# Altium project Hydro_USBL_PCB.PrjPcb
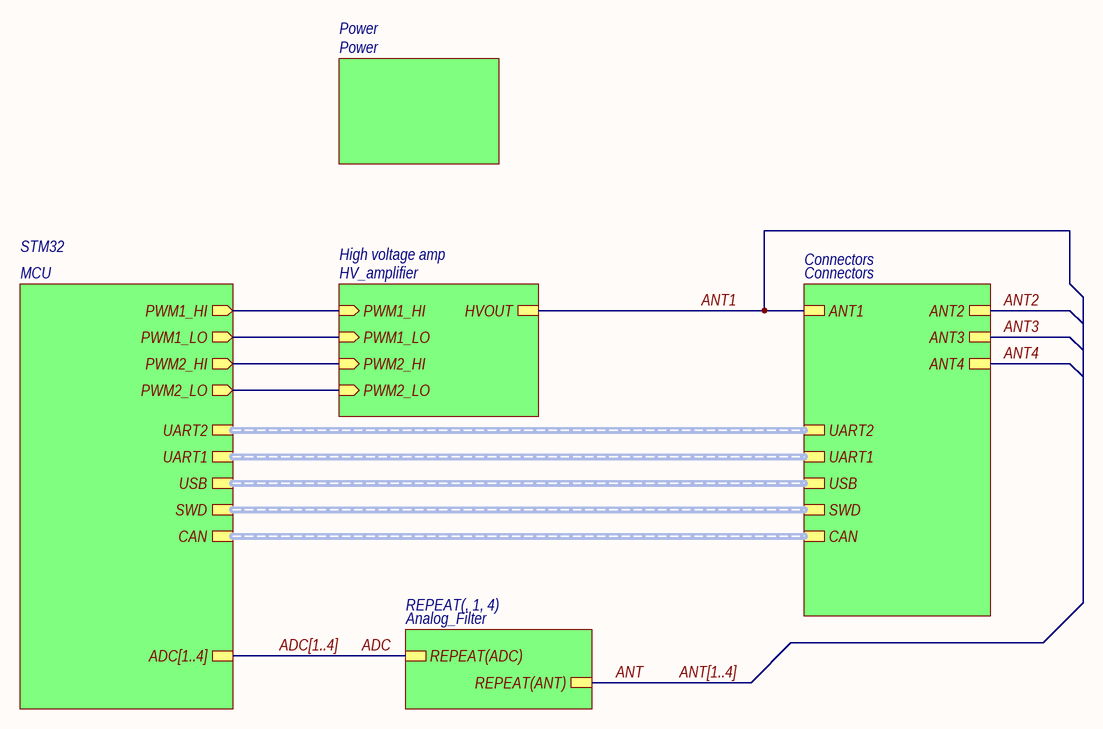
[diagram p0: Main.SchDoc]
Decimal_Number_PCB: ГИДР.123456.XXX; Decimal_Number_Shematic: ГИДР.123456.XXX; DrawnBy: Михайловский Г.; Release_Date: ???; Title: ГАНС с короткой или ультракороткой базой; Title1: Преобразователь из; Title2: 15В в 300В; Version: 01
6 sheets, 273 parts. Net scope: hierarchical (ports join the sheet entries above them; power ports are global).
Board file: Hydro_USBL_PCB.PcbDoc
Sheets:
  Main.SchDoc
    Connectors = Connectors.SchDoc
    1 = Analog_Filter.SchDoc
    2 = Analog_Filter.SchDoc
    3 = Analog_Filter.SchDoc
    4 = Analog_Filter.SchDoc
    Power = Power.SchDoc
    High voltage amp = HV_amplifier.SchDoc
    STM32 = MCU.SchDoc

## Sheet Main.SchDoc: ГАНС с короткой или ультракороткой базой
size 420 x 297 mm; SheetNumber: 1; SheetTotal: 6

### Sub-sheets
Connectors = Connectors: ANT1, ANT2, ANT3, ANT4, SWD (harness SWD), UART2 (harness UART), USB (harness USB), UART1 (harness UART-RS485), CAN (harness CAN)
High voltage amp = HV_amplifier: HVOUT, PWM1_HI (in), PWM1_LO (in), PWM2_HI (in), PWM2_LO (in)
Power = Power: no entries
REPEAT(, 1, 4) = Analog_Filter: REPEAT(ADC), REPEAT(ANT)
STM32 = MCU: PWM1_HI (out), PWM1_LO (out), PWM2_HI (out), PWM2_LO (out), ADC[1..4], UART2 (harness UART), UART1 (harness UART-RS485), USB (harness USB), SWD (harness SWD), CAN (harness CAN)

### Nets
ANT1: sheet Connectors/ANT1, sheet High voltage amp/HVOUT
PWM1_HI: sheet High voltage amp/PWM1_HI, sheet STM32/PWM1_HI
PWM1_LO: sheet High voltage amp/PWM1_LO, sheet STM32/PWM1_LO
PWM2_HI: sheet High voltage amp/PWM2_HI, sheet STM32/PWM2_HI
PWM2_LO: sheet High voltage amp/PWM2_LO, sheet STM32/PWM2_LO

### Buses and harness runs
bus ADC[1..4] = sheet STM32/ADC[1..4]
bus ANT[1..4]
harness sheet Connectors/CAN = sheet STM32/CAN
harness sheet Connectors/SWD = sheet STM32/SWD
harness sheet Connectors/UART1 = sheet STM32/UART1
harness sheet Connectors/UART2 = sheet STM32/UART2
harness sheet Connectors/USB = sheet STM32/USB

## Sheet Connectors.SchDoc: ГАНС с короткой или ультракороткой базой
size 420 x 297 mm; SheetNumber: 6; SheetTotal: 6
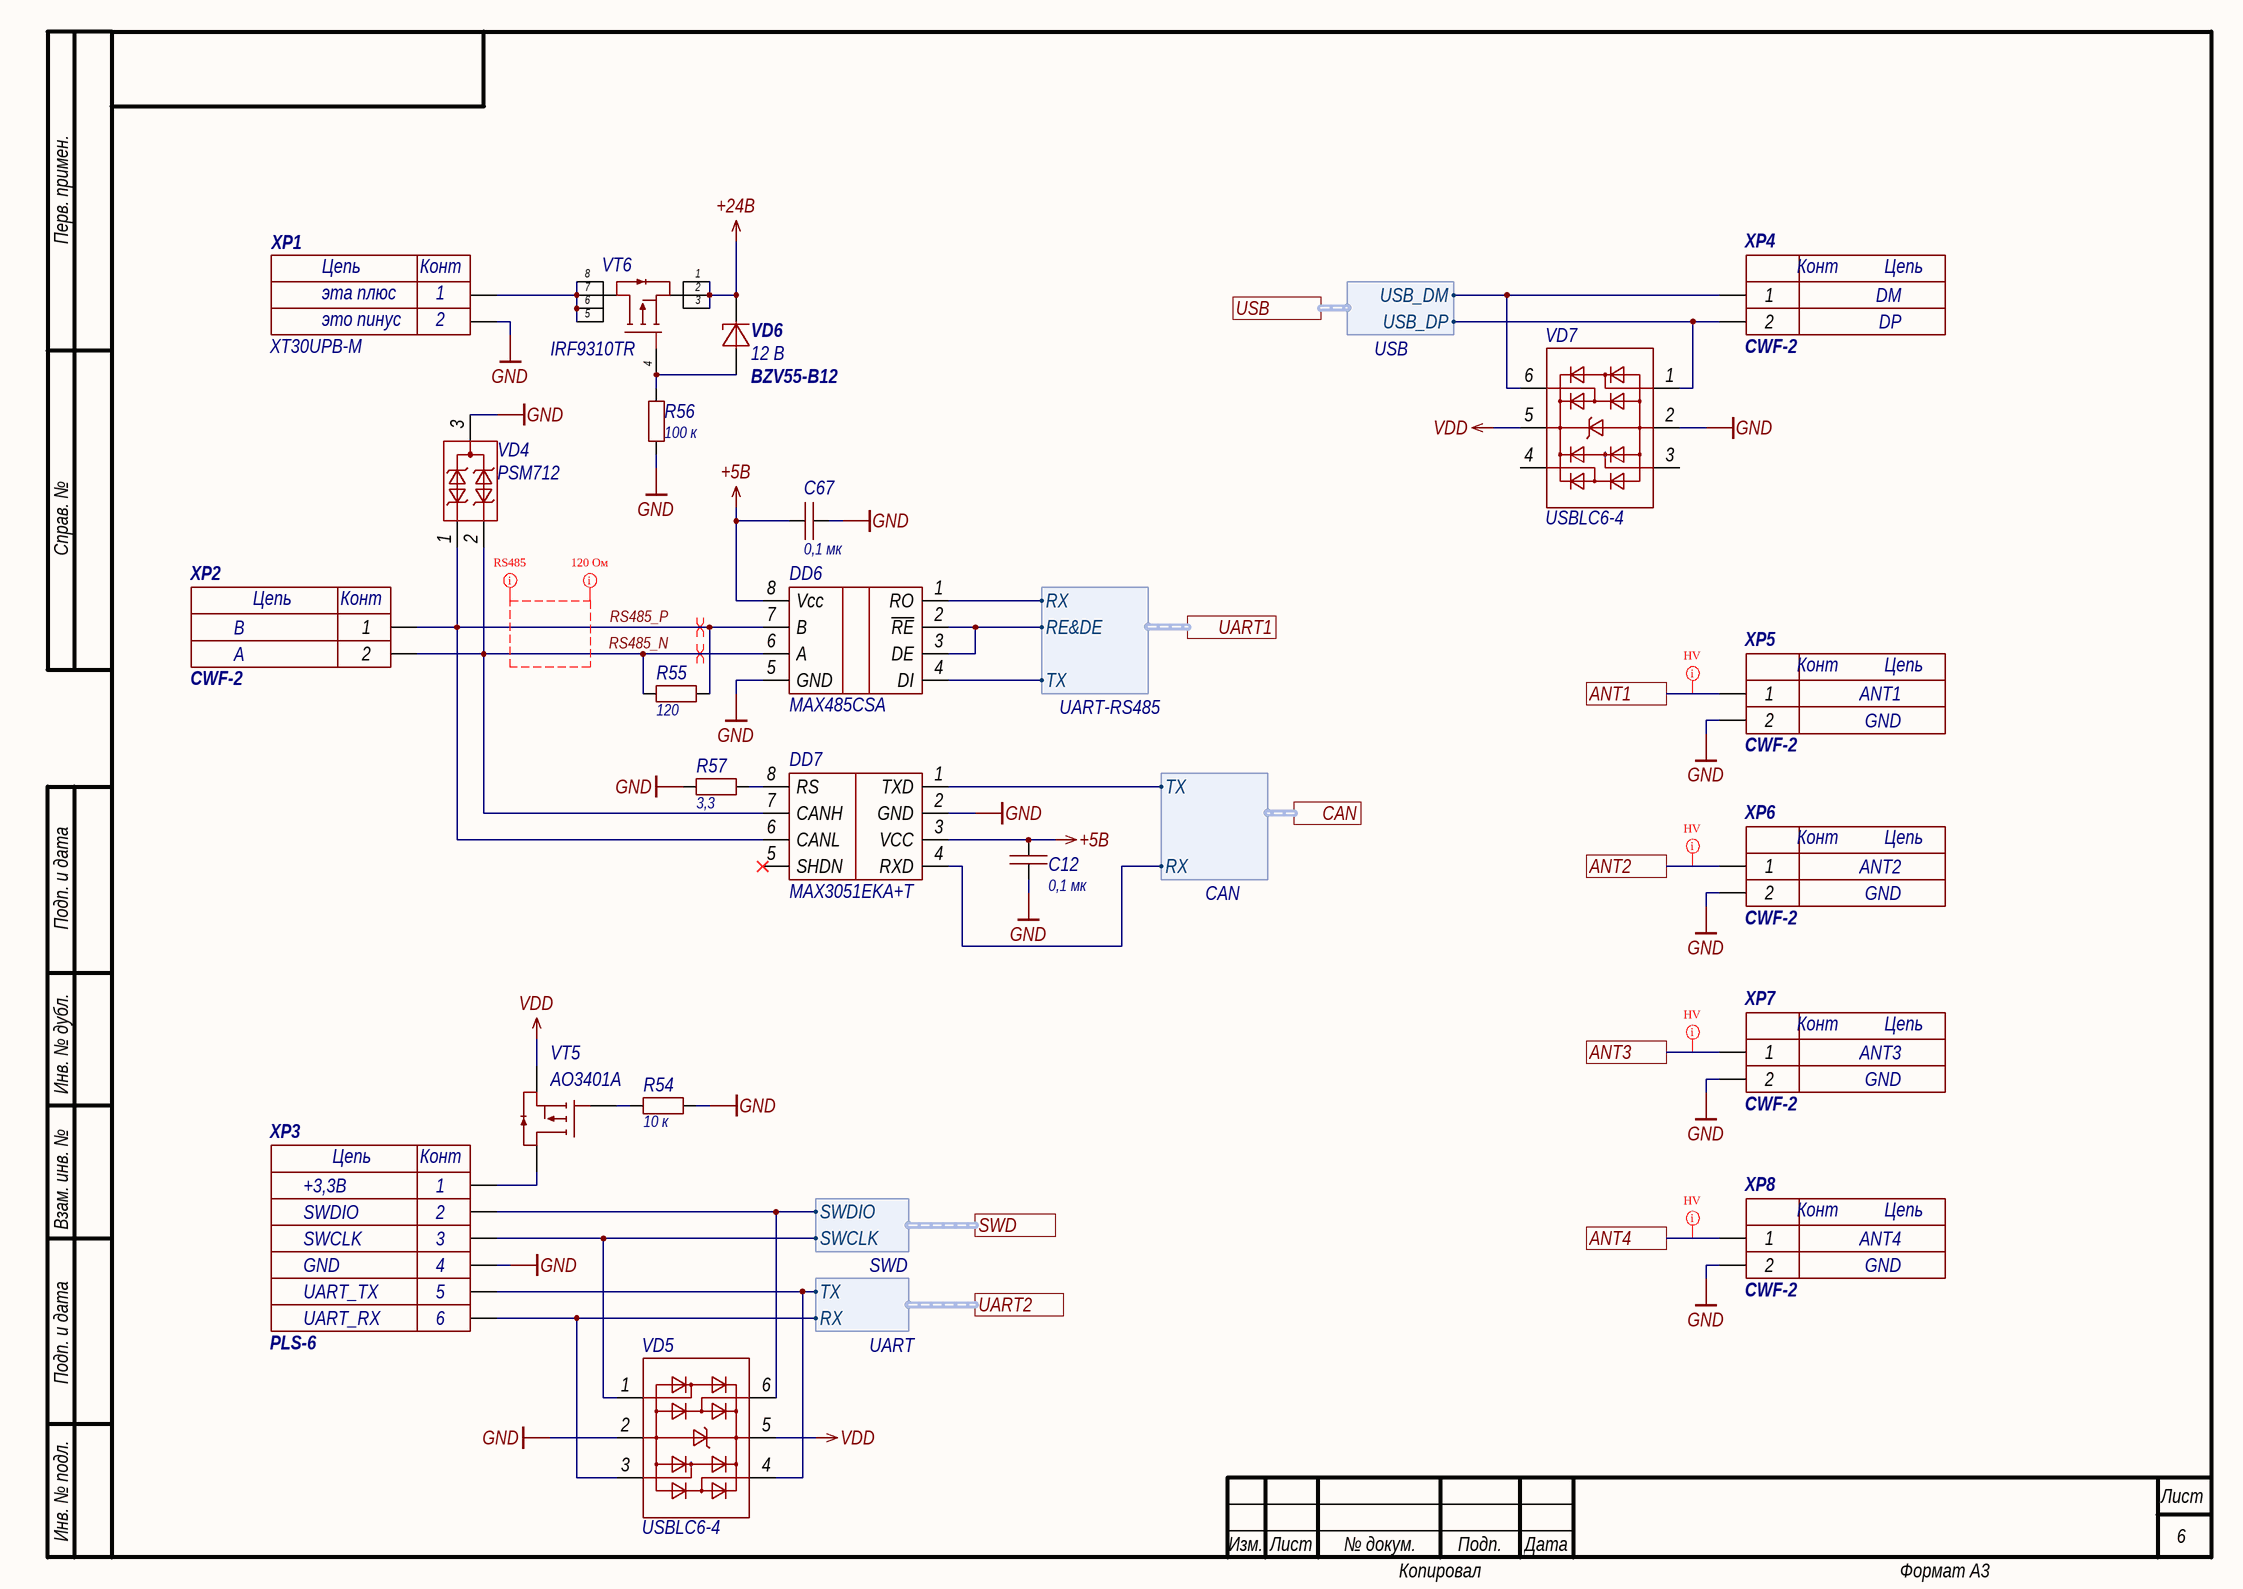
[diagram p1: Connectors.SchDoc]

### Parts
C12  value 0,1 мк  [0603C]  (hidden comment: Capacitor)
C67  value 0,1 мк  [0603C]  (hidden comment: Capacitor)
DD6  MAX485CSA  [SOIC-8]
DD7  MAX3051EKA+T  [SOT23-8]
R54  value 10 к  [0603R]  (hidden comment: Resistor)
R55  value 120  [1206R]  (hidden comment: Resistor)
R56  value 100 к  [0603R]  (hidden comment: Resistor)
R57  value 3,3  [0603R]  (hidden comment: Resistor)
VD4  PSM712  [SOT23-3]
VD5  USBLC6-4  [SOT23-6]
VD6  BZV55-B12  value 12 В  [mini_MELF_3.5mm]
VD7  USBLC6-4  [SOT23-6]
VT5  AO3401A  [SOT23-3]
VT6  IRF9310TR  [SOIC-8]
XP1  XT30UPB-M  Value2: это пинус  Value1: эта плюс  [XT30UPB-M]
XP2  CWF-2  Value2: A  Value1: B  [CWF-2]
XP3  PLS-6  Value1: +3,3В  Value2: SWDIO  Value3: SWCLK  Value4: GND  Value5: UART_TX  Value6: UART_RX  [PLS6]
XP4  CWF-2  Value2: DP  Value1: DM  [CWF-2]
XP5  CWF-2  Value2: GND  Value1: ANT1  [CWF-2]
XP6  CWF-2  Value2: GND  Value1: ANT2  [CWF-2]
XP7  CWF-2  Value2: GND  Value1: ANT3  [CWF-2]
XP8  CWF-2  Value2: GND  Value1: ANT4  [CWF-2]

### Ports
ANT1, ANT2, ANT3, ANT4, CAN (harness CAN), SWD (harness SWD), UART1 (harness UART-RS485), UART2 (harness UART), USB (harness USB)

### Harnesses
SWD: SWDIO, SWCLK
UART: TX, RX
USB: USB_DM, USB_DP
UART-RS485: TX, RX, RE&DE
CAN: TX, RX

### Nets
+5В: C12.2 C67.1 DD6.8(Vcc) DD7.3(VCC)
+24В: VD6.2 VT6.1 VT6.2 VT6.3
GND: C12.1 C67.2 DD6.5(GND) DD7.2(GND) R54.1 R56.1 R57.1 VD4.3 VD5.2 VD7.2 XP1.N XP3.4 XP5.2 XP6.2 XP7.2 XP8.2
VDD: VD5.5 VD7.5 VT5.2
ANT1: XP5.1 ; port ANT1
ANT2: XP6.1 ; port ANT2
ANT3: XP7.1 ; port ANT3
ANT4: XP8.1 ; port ANT4
CAN_RX: DD7.1(TXD) ; port CAN.TX
CAN_TX: DD7.4(RXD) ; port CAN.RX
RE&DE: DD6.2(~{RE}) DD6.3(DE) ; port UART1.RE&DE
RS485_N: DD6.6(A) DD7.7(CANH) R55.1 VD4.2 XP2.2  [project net RS485_N_6]
RS485_P: DD6.7(B) DD7.6(CANL) R55.2 VD4.1 XP2.1  [project net RS485_P_6]
SWCLOCK: VD5.1 XP3.3 ; port SWD.SWCLK
SWDIO: VD5.6 XP3.2 ; port SWD.SWDIO
UART1_RX: DD6.1(RO) ; port UART1.RX
UART1_TX: DD6.4(DI) ; port UART1.TX
UART2_RX: VD5.3 XP3.6 ; port UART2.RX
UART2_TX: VD5.4 XP3.5 ; port UART2.TX
USB_N: VD7.6 XP4.1 ; port USB.USB_DM
USB_P: VD7.1 XP4.2 ; port USB.USB_DP
NetDD7_8: DD7.8(RS) R57.2
NetR54_2: R54.2 VT5.1
NetR56_2: R56.2 VD6.1 VT6.4
NetVT5_3: VT5.3 XP3.1
NetVT6_5: VT6.5 VT6.6 VT6.7 VT6.8 XP1.P

Not connected (* = marked no-connect by the designer): DD7 5(SHDN)*; VD7 3(11) 4(12)

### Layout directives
differential pair: RS485_N_6, RS485_P_6
mark named RS485: (no net found under the mark)
net class 120OhmDiff: (no net found under the mark)
net class HV; rule Clearance Constraint [Clearance = 1mm]: ANT1, ANT2, ANT3, ANT4

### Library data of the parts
C12 C67 = Capacitor_0,1u_10_50V_X7R_0603C: Конденсатор 0603C ёмкостью 0,1 мк 10%, 50 В, X7R; Voltage (V): 50; Capacity (nF): 100
DD6 = MAX485CSA: RS-485 приёмопередатчик
DD7 = MAX3051EKA+T: CAN трансивер 1Mbps +3.3В; Автор: glebmih
R54 = Resistor_10k_1_0603: Резистор номиналом 10 кОм 1%
R55 = Resistor_120_1_1206: Резистор номиналом 120 Ом 1%; Автор: glebmih
R56 = Resistor_100k_1_0603: Резистор номиналом 100 кОм 1%
R57 = Resistor_3.3_1_0603: Резистор номиналом 3,3 Ом 1%
VD4 = PSM712: Защитный диод для линии RS-485
VD5 VD7 = USBLC6-4: Сборка защитных диодов для USB
VD6 = BZV55-B12: Стабилитрон 12В, 5%, 0.5Вт; Voltage (V): 12; Current: 5 мА; Power (W): 0.5; Accuracy: 0,02; Автор: rreali
VT5 = AO3401A: P-канальный MOSFET
VT6 = IRF9310TR: P-канальный MOSFET, 30 В, 20 А; Voltage (V): 30 В; Current (A): 20 А; Автор: glebmih
XP1 = XT30UPB-M: 2-пиновый разъем с ключом; System: Connector; Автор: rreali
XP2 XP4-XP8 = CWF-2: 2-пиновый разъем с ключом; System: Connector; Автор: rreali
XP3 = PLS-6: Гребенка 6 пинов; System: Connector; Автор: glebmih

## Sheet Analog_Filter.SchDoc: ГАНС с короткой или ультракороткой базой
size 420 x 297 mm; SheetNumber: 3; SheetTotal: 6
Used 4 times, as channels 1, 2, 3, 4. Parts and nets are listed once, with the designators drawn on the sheet.
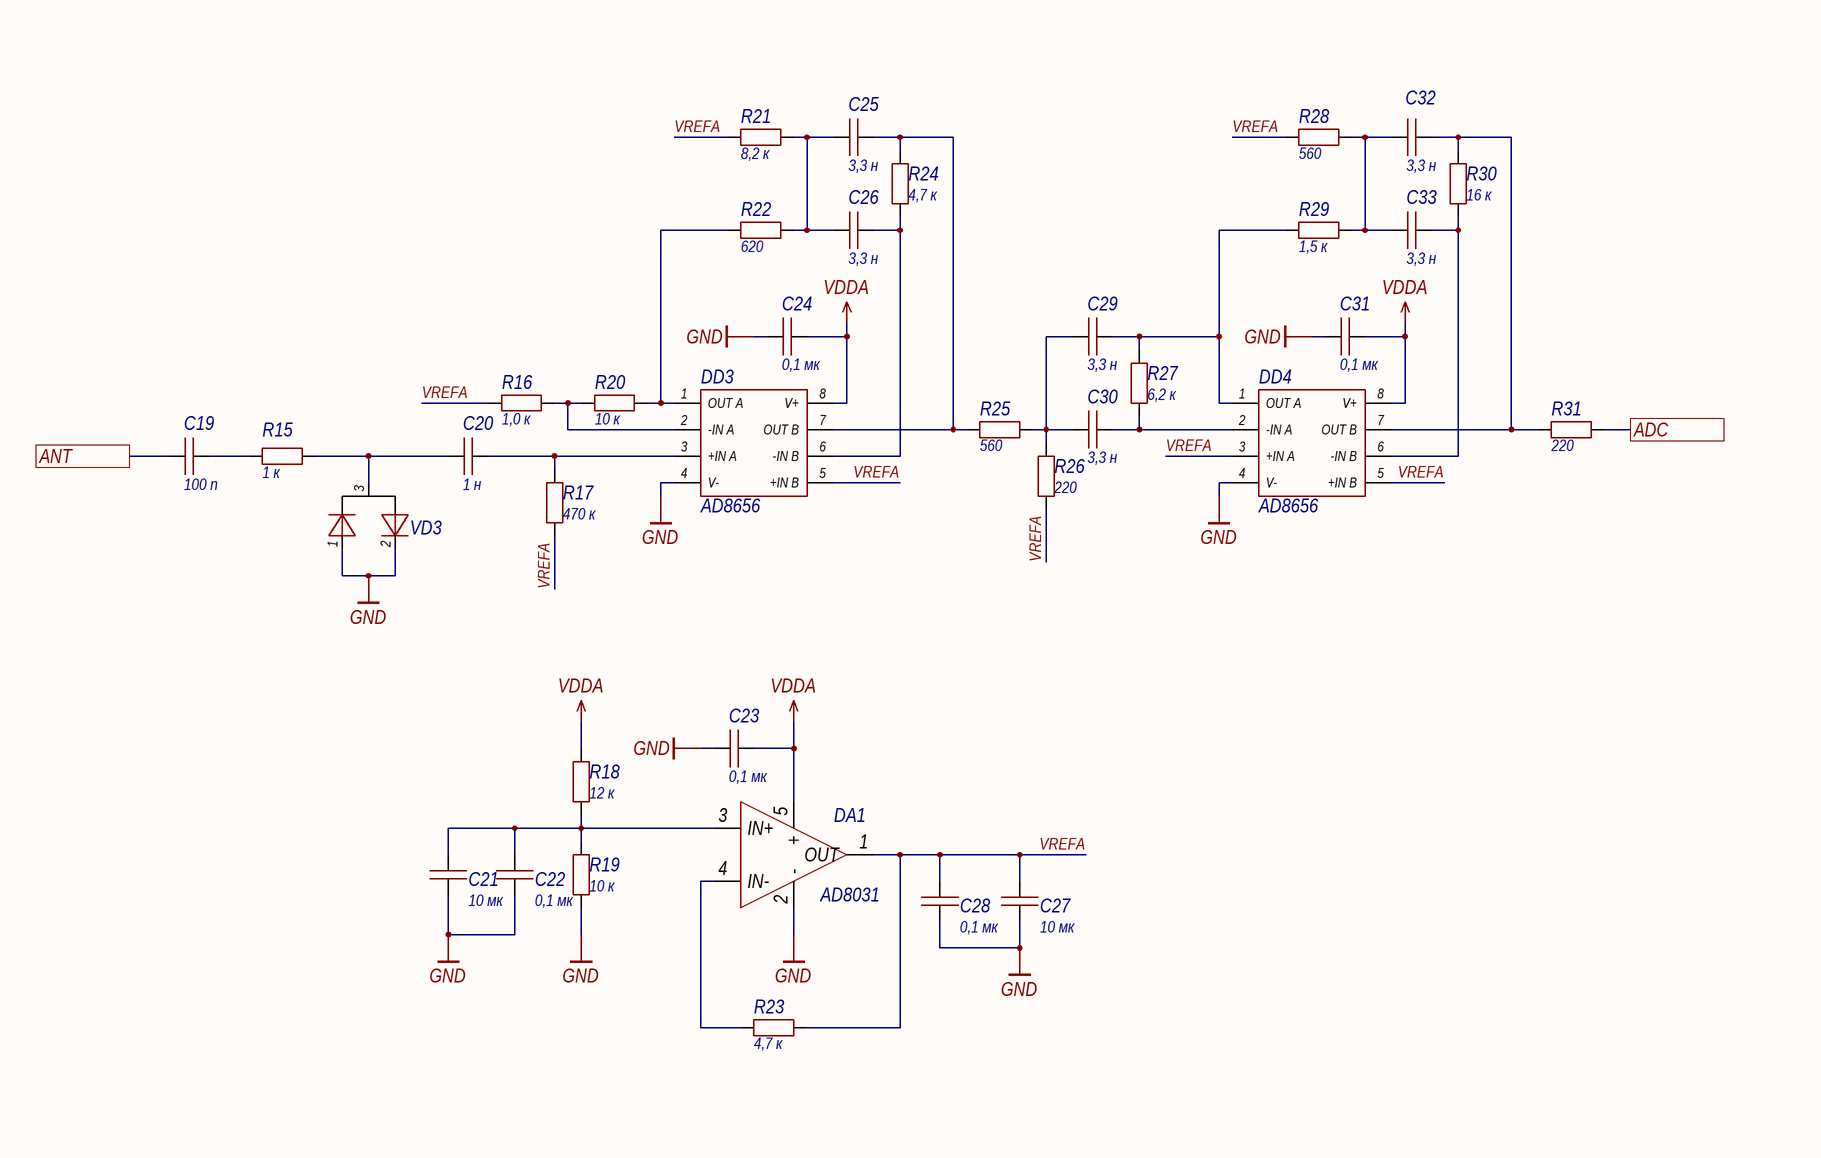
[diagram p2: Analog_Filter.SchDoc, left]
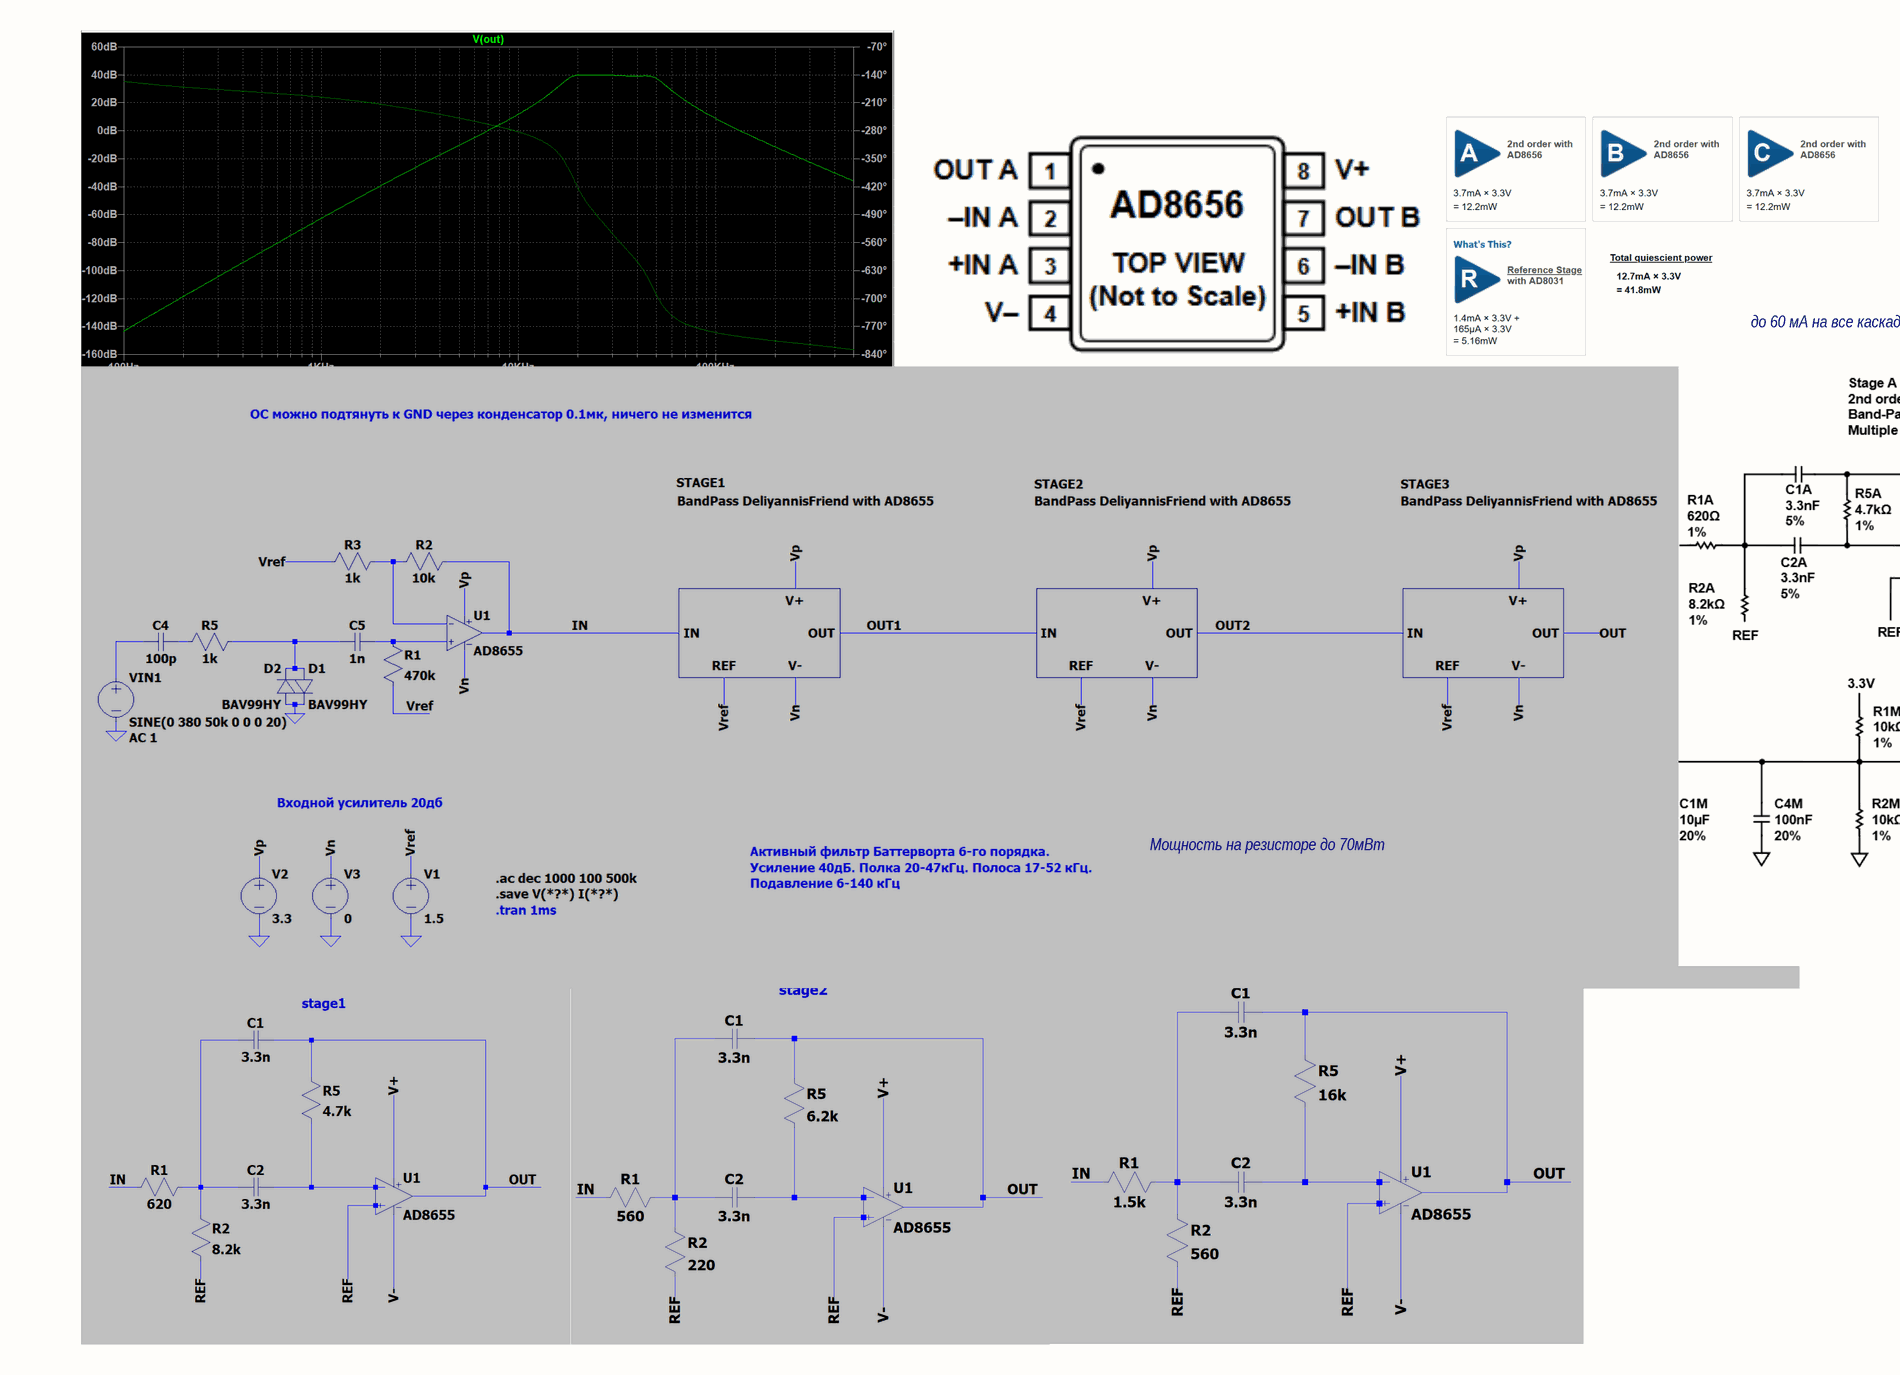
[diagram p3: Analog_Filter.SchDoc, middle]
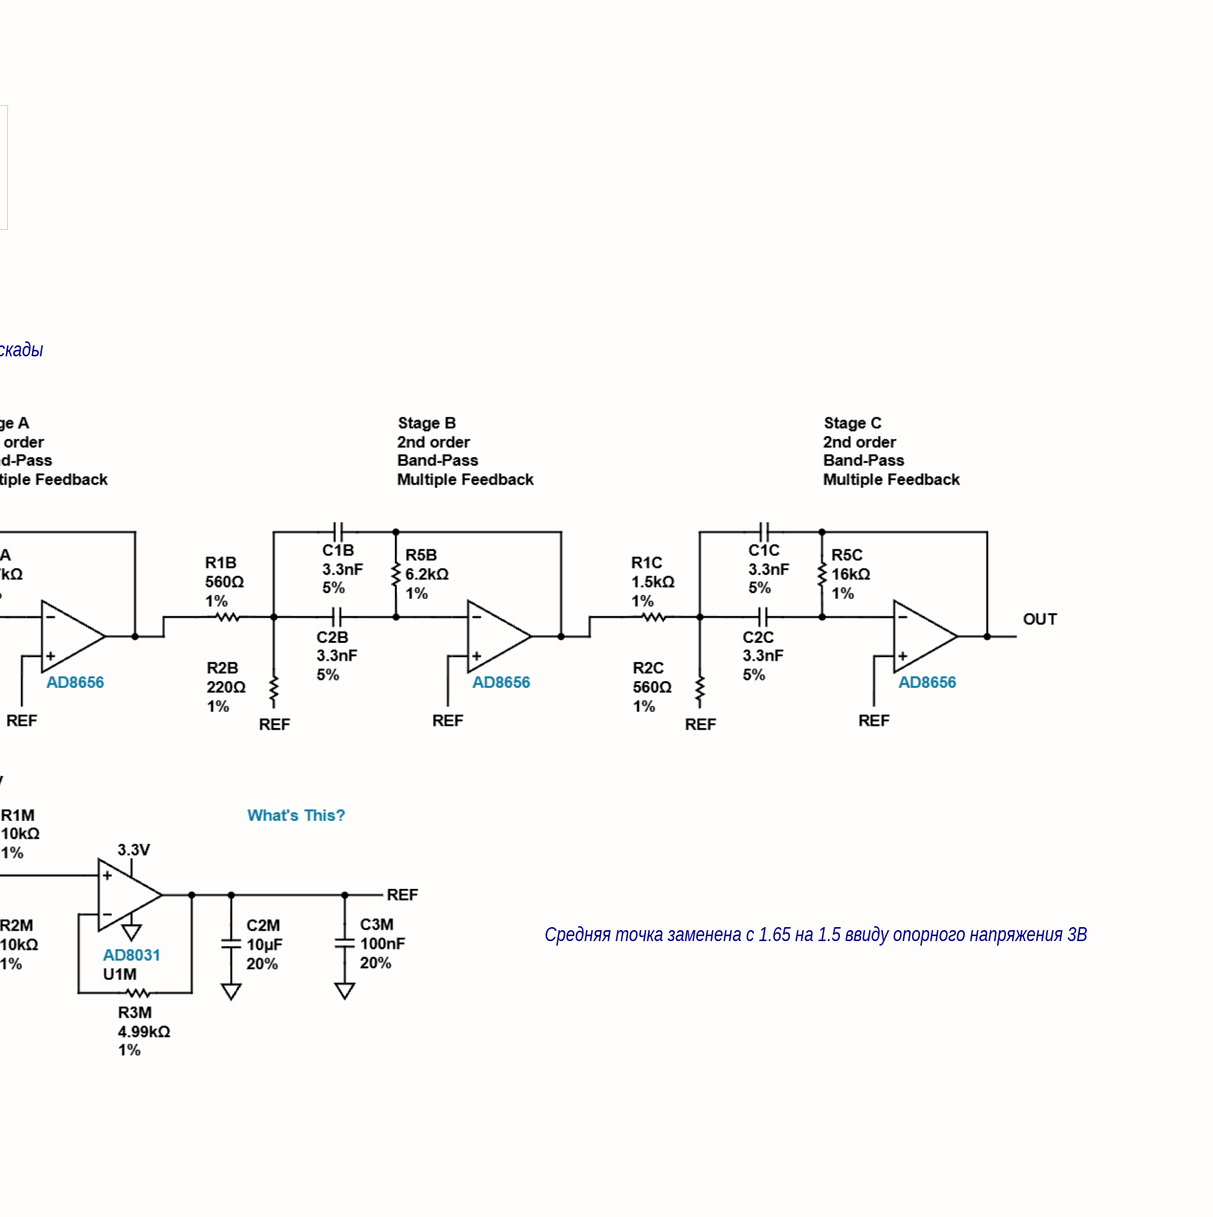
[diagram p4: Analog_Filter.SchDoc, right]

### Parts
C19  value 100 п  [1206C]  (hidden comment: Capacitor)
C20  value 1 н  [0603C]  (hidden comment: Capacitor)
C21  value 10 мк  [0603C]  (hidden comment: Capacitor)
C22  value 0,1 мк  [0603C]  (hidden comment: Capacitor)
C23  value 0,1 мк  [0603C]  (hidden comment: Capacitor)
C24  value 0,1 мк  [0603C]  (hidden comment: Capacitor)
C25  value 3,3 н  [0603C]  (hidden comment: Capacitor)
C26  value 3,3 н  [0603C]  (hidden comment: Capacitor)
C27  value 10 мк  [0603C]  (hidden comment: Capacitor)
C28  value 0,1 мк  [0603C]  (hidden comment: Capacitor)
C29  value 3,3 н  [0603C]  (hidden comment: Capacitor)
C30  value 3,3 н  [0603C]  (hidden comment: Capacitor)
C31  value 0,1 мк  [0603C]  (hidden comment: Capacitor)
C32  value 3,3 н  [0603C]  (hidden comment: Capacitor)
C33  value 3,3 н  [0603C]  (hidden comment: Capacitor)
DA1  AD8031  [SOT23-5]
DD3  AD8656  [SOIC-8]
DD4  AD8656  [SOIC-8]
R15  value 1 к  [0805R]  (hidden comment: Resistor)
R16  value 1,0 к  [0603R]  (hidden comment: Resistor)
R17  value 470 к  [0603R]  (hidden comment: Resistor)
R18  value 12 к  [0603R]  (hidden comment: Resistor)
R19  value 10 к  [0603R]  (hidden comment: Resistor)
R20  value 10 к  [0603R]  (hidden comment: Resistor)
R21  value 8,2 к  [0603R]  (hidden comment: Resistor)
R22  value 620  [0603R]  (hidden comment: Resistor)
R23  value 4,7 к  [0603R]  (hidden comment: Resistor)
R24  value 4,7 к  [0603R]  (hidden comment: Resistor)
R25  value 560  [0603R]  (hidden comment: Resistor)
R26  value 220  [0603R]  (hidden comment: Resistor)
R27  value 6,2 к  [0603R]  (hidden comment: Resistor)
R28  value 560  [0603R]  (hidden comment: Resistor)
R29  value 1,5 к  [0603R]  (hidden comment: Resistor)
R30  value 16 к  [0603R]  (hidden comment: Resistor)
R31  value 220  [0603R]  (hidden comment: Resistor)
VD3  BAV99  [SOT23-3]  (value not drawn)

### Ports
ADC, ANT

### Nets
GND: C21.1 C22.1 C23.1 C24.1 C27.1 C28.1 C31.1 DA1.2(-) DD3.4(V-) DD4.4(V-) R19.1 VD3.1 VD3.2
VDDA: C23.2 C24.2 C31.2 DA1.5(+) DD3.8(V+) DD4.8(V+) R18.2
ADC: R31.2 ; port ADC
ANT: C19.1 ; port ANT
VREFA: C27.2 C28.2 DA1.1(OUT) DD3.5(+IN_B) DD4.3(+IN_A) DD4.5(+IN_B) R16.1 R17.1 R21.2 R23.2 R26.1 R28.1  [project net VREFA_3]
NetC19_2: C19.2 R15.1
NetC20_1: C20.1 R15.2 VD3.3
NetC20_2: C20.2 DD3.3(+IN_A) R17.2
NetC21_2: C21.2 C22.2 DA1.3(IN+) R18.1 R19.2
NetC25_1: C25.1 C26.1 R21.1 R22.2
NetC25_2: C25.2 DD3.7(OUT_B) R24.1 R25.1
NetC26_2: C26.2 DD3.6(-IN_B) R24.2
NetC29_1: C29.1 C30.1 R25.2 R26.2
NetC29_2: C29.2 DD4.1(OUT_A) R27.2 R29.1
NetC30_2: C30.2 DD4.2(-IN_A) R27.1
NetC32_1: C32.1 C33.1 R28.2 R29.2
NetC32_2: C32.2 DD4.7(OUT_B) R30.2 R31.1
NetC33_2: C33.2 DD4.6(-IN_B) R30.1
NetDA1_4: DA1.4(IN-) R23.1
NetDD3_1: DD3.1(OUT_A) R20.2 R22.1
NetDD3_2: DD3.2(-IN_A) R16.2 R20.1

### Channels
1: designators end in A; ports ADC=ADC1 ANT=ANT1
2: designators end in B; ports ADC=ADC2 ANT=ANT2
3: designators end in C; ports ADC=ADC3 ANT=ANT3
4: designators end in D; ports ADC=ADC4 ANT=ANT4

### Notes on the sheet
- до 60 мА на все каскады
- Мощность на резисторе до 70мВт
- Средняя точка заменена с 1.65 на 1.5 ввиду опорного напряжения 3В

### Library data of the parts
C19 = Capacitor_100p_5_630V_NP0_1206C: Конденсатор 1206C ёмкостью 100 п 5%, 630 В, NP0; Voltage (V): 630; Capacity (nF): 0,1; Автор: glebmih
C20 = Capacitor_1n_5_50V_NP0_0603C: Конденсатор 0603C ёмкостью 1 н 5%, 50 В, NP0; Voltage (V): 50; Capacity (nF): 1; Автор: glebmih
C21 C27 = Capacitor_10u_10_10V_X7R_0603C: Конденсатор 0603C ёмкостью 10 мк 10%, 10 В, X7R; Voltage (V): 10; Capacity (nF): 10000; Автор: glebmih
C22-C24 C28 C31 = Capacitor_0,1u_10_50V_X7R_0603C: as C12 on sheet Connectors
C25 C26 C29 C30 C32 C33 = Capacitor_3.3n_5_50V_NP0_0603C: Конденсатор 0603C ёмкостью 3,3 н 5%, 50 В, NP0; Voltage (V): 50; Capacity (nF): 3,3; Автор: glebmih
DA1 = AD8031: Операционный усилитель, 80МГц, 1-канал, 35В/мкс, Voltage Feedback, Rail-to-Rail; Автор: glebmih
DD3 DD4 = AD8656: Операционный усилитель 28МГц, CMOS, 2-канала, Rail-to-Rail; Автор: glebmih
R15 = Resistor_1k_0805: Резистор номиналом 1 кОм 1%; Автор: glebmih
R16 = Resistor_1.0k_1_0603: Резистор номиналом 1,0 кОм 1%
R17 = Resistor_470k_1_0603: Резистор номиналом 470 кОм 1%
R18 = Resistor_12k_1_0603: Резистор номиналом 12 кОм 1%
R19 R20 = Resistor_10k_1_0603: Резистор номиналом 10 кОм 1%
R21 = Resistor_8.2k_1_0603: Резистор номиналом 8,2 кОм 1%
R22 = Resistor_620_1_0603: Резистор номиналом 620 Ом 1%
R23 R24 = Resistor_4.7k_1_0603: Резистор номиналом 4,7 кОм 1%
R25 R28 = Resistor_560_1_0603: Резистор номиналом 560 Ом 1%
R26 R31 = Resistor_220_1_0603: Резистор номиналом 220 Ом 1%
R27 = Resistor_6.2k_1_0603: Резистор номиналом 6,2 кОм 1%
R29 = Resistor_1.5k_1_0603: Резистор номиналом 1,5 кОм 1%
R30 = Resistor_16k_1_0603: Резистор номиналом 16 кОм 1%
VD3 = BAV99: Диод импульсный, 2 х 0.2А, 70В, последовательное включение; Voltage (V): 70; Current: 0.2; Автор: glebmih

## Sheet Power.SchDoc: ГАНС с короткой или ультракороткой базой
size 420 x 297 mm; SheetNumber: 5; SheetTotal: 6
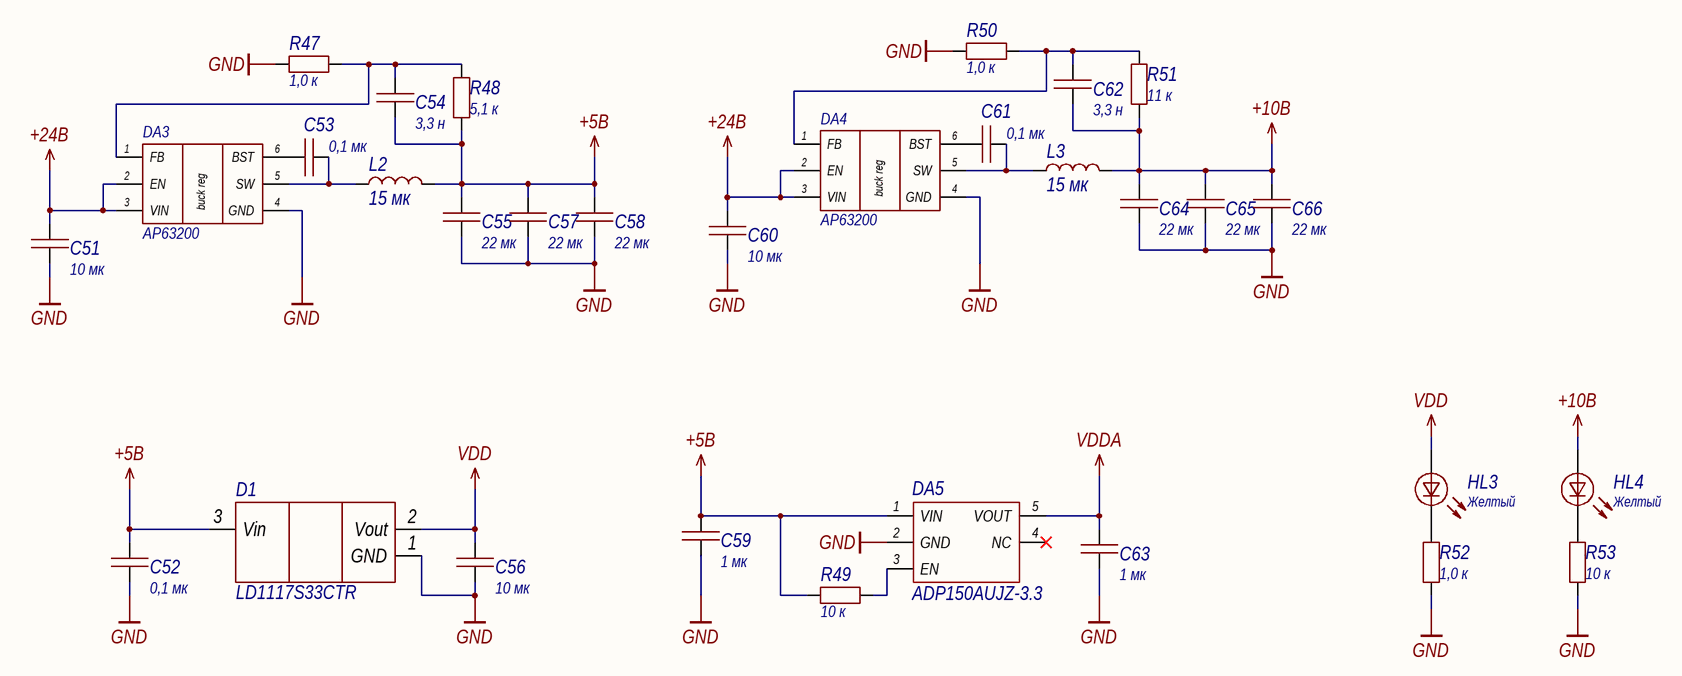
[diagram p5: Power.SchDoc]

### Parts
C51  value 10 мк  [1210C]  (hidden comment: Capacitor)
C52  value 0,1 мк  [0603C]  (hidden comment: Capacitor)
C53  value 0,1 мк  [0603C]  (hidden comment: Capacitor)
C54  value 3,3 н  [0603C]  (hidden comment: Capacitor)
C55  value 22 мк  [1210C]  (hidden comment: Capacitor)
C56  value 10 мк  [1210C]  (hidden comment: Capacitor)
C57  value 22 мк  [1210C]  (hidden comment: Capacitor)
C58  value 22 мк  [1210C]  (hidden comment: Capacitor)
C59  value 1 мк  [0603C]  (hidden comment: Capacitor)
C60  value 10 мк  [1210C]  (hidden comment: Capacitor)
C61  value 0,1 мк  [0603C]  (hidden comment: Capacitor)
C62  value 3,3 н  [0603C]  (hidden comment: Capacitor)
C63  value 1 мк  [0603C]  (hidden comment: Capacitor)
C64  value 22 мк  [1210C]  (hidden comment: Capacitor)
C65  value 22 мк  [1210C]  (hidden comment: Capacitor)
C66  value 22 мк  [1210C]  (hidden comment: Capacitor)
D1  LD1117S33CTR  [SOT223]
DA3  AP63200  [TSOT26]
DA4  AP63200  [TSOT26]
DA5  ADP150AUJZ-3.3  [SOT23-5]
HL3  value Желтый  [0805D]  (hidden comment: LED)
HL4  value Желтый  [0805D]  (hidden comment: LED)
L2  value 15 мк  [SP43]  (hidden comment: SP43-150K)
L3  value 15 мк  [SP43]  (hidden comment: SP43-150K)
R47  value 1,0 к  [0603R]  (hidden comment: Resistor)
R48  value 5,1 к  [0603R]  (hidden comment: Resistor)
R49  value 10 к  [0603R]  (hidden comment: Resistor)
R50  value 1,0 к  [0603R]  (hidden comment: Resistor)
R51  value 11 к  [0603R]  (hidden comment: Resistor)
R52  value 1,0 к  [0603R]  (hidden comment: Resistor)
R53  value 10 к  [0603R]  (hidden comment: Resistor)

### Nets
+5В: C52.2 C54.2 C55.2 C57.2 C58.2 C59.2 D1.3(Vin) DA5.1(VIN) L2.2 R48.2 R49.2
+10В: C62.2 C64.2 C65.2 C66.2 HL4.1 L3.2 R51.1
+24В: C51.2 C60.2 DA3.2(EN) DA3.3(VIN) DA4.2(EN) DA4.3(VIN)
GND: C51.1 C52.1 C55.1 C56.1 C57.1 C58.1 C59.1 C60.1 C63.1 C64.1 C65.1 C66.1 D1.1(GND) DA3.4(GND) DA4.4(GND) DA5.2(GND) R47.1 R50.1 R52.1 R53.1
VDD: C56.2 D1.2(Vout) HL3.1
VDDA: C63.2 DA5.5(VOUT)
NetC53_1: C53.1 DA3.6(BST)
NetC53_2: C53.2 DA3.5(SW) L2.1
NetC54_1: C54.1 DA3.1(FB) R47.2 R48.1
NetC61_1: C61.1 DA4.6(BST)
NetC61_2: C61.2 DA4.5(SW) L3.1
NetC62_1: C62.1 DA4.1(FB) R50.2 R51.2
NetDA5_3: DA5.3(EN) R49.1
NetHL3_2: HL3.2 R52.2
NetHL4_2: HL4.2 R53.2

Not connected (* = marked no-connect by the designer): DA5 4(NC)*

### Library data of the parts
C51 C56 C60 = Capacitor_10u_10_35V_X7R_1210C: Конденсатор 1210C ёмкостью 10 мк 10%, 35 В, X7R; Voltage (V): 35; Capacity (nF): 10000
C52 C53 C61 = Capacitor_0,1u_10_50V_X7R_0603C: as C12 on sheet Connectors
C54 C62 = Capacitor_3.3n_5_50V_NP0_0603C: as C25 on sheet Analog_Filter
C55 C57 C58 C64-C66 = Capacitor_22u_10_25V_X7R_1210C: Конденсатор 1210C ёмкостью 22 мк 10%, 25 В, X7R; Voltage (V): 25; Capacity (nF): 22000
C59 C63 = Capacitor_1u_10_25V_X7R_0603C: Конденсатор 0603C ёмкостью 1 мк 10%, 25 В, X7R; Voltage (V): 25; Capacity (nF): 1000
D1 = LD1117S33CTR: Линейный стабилизатор напряжения
DA3 DA4 = AP63200: DC-DC понижающий преобразователь, Vin: 3.8 - 40 В, adj, 2 А
DA5 = ADP150AUJZ-3.3: Стабилизатор напряжения 3.3В 150мА; Автор: glebmih
HL3 HL4 = LED: Светодиод
L2 L3 = SP43-150K: Индуктивность на 15 мкГн, номинальный ток 1,3 А; Inductance (μH): 15; Current: 1,3 А
R47 R50 R52 = Resistor_1.0k_1_0603: Резистор номиналом 1,0 кОм 1%
R48 = Resistor_5.1k_1_0603: Резистор номиналом 5,1 кОм 1%
R49 R53 = Resistor_10k_1_0603: Резистор номиналом 10 кОм 1%
R51 = Resistor_11k_1_0603: Резистор номиналом 11 кОм 1%

## Sheet HV_amplifier.SchDoc: ГАНС с короткой или ультракороткой базой
size 420 x 297 mm; SheetNumber: 2; SheetTotal: 6
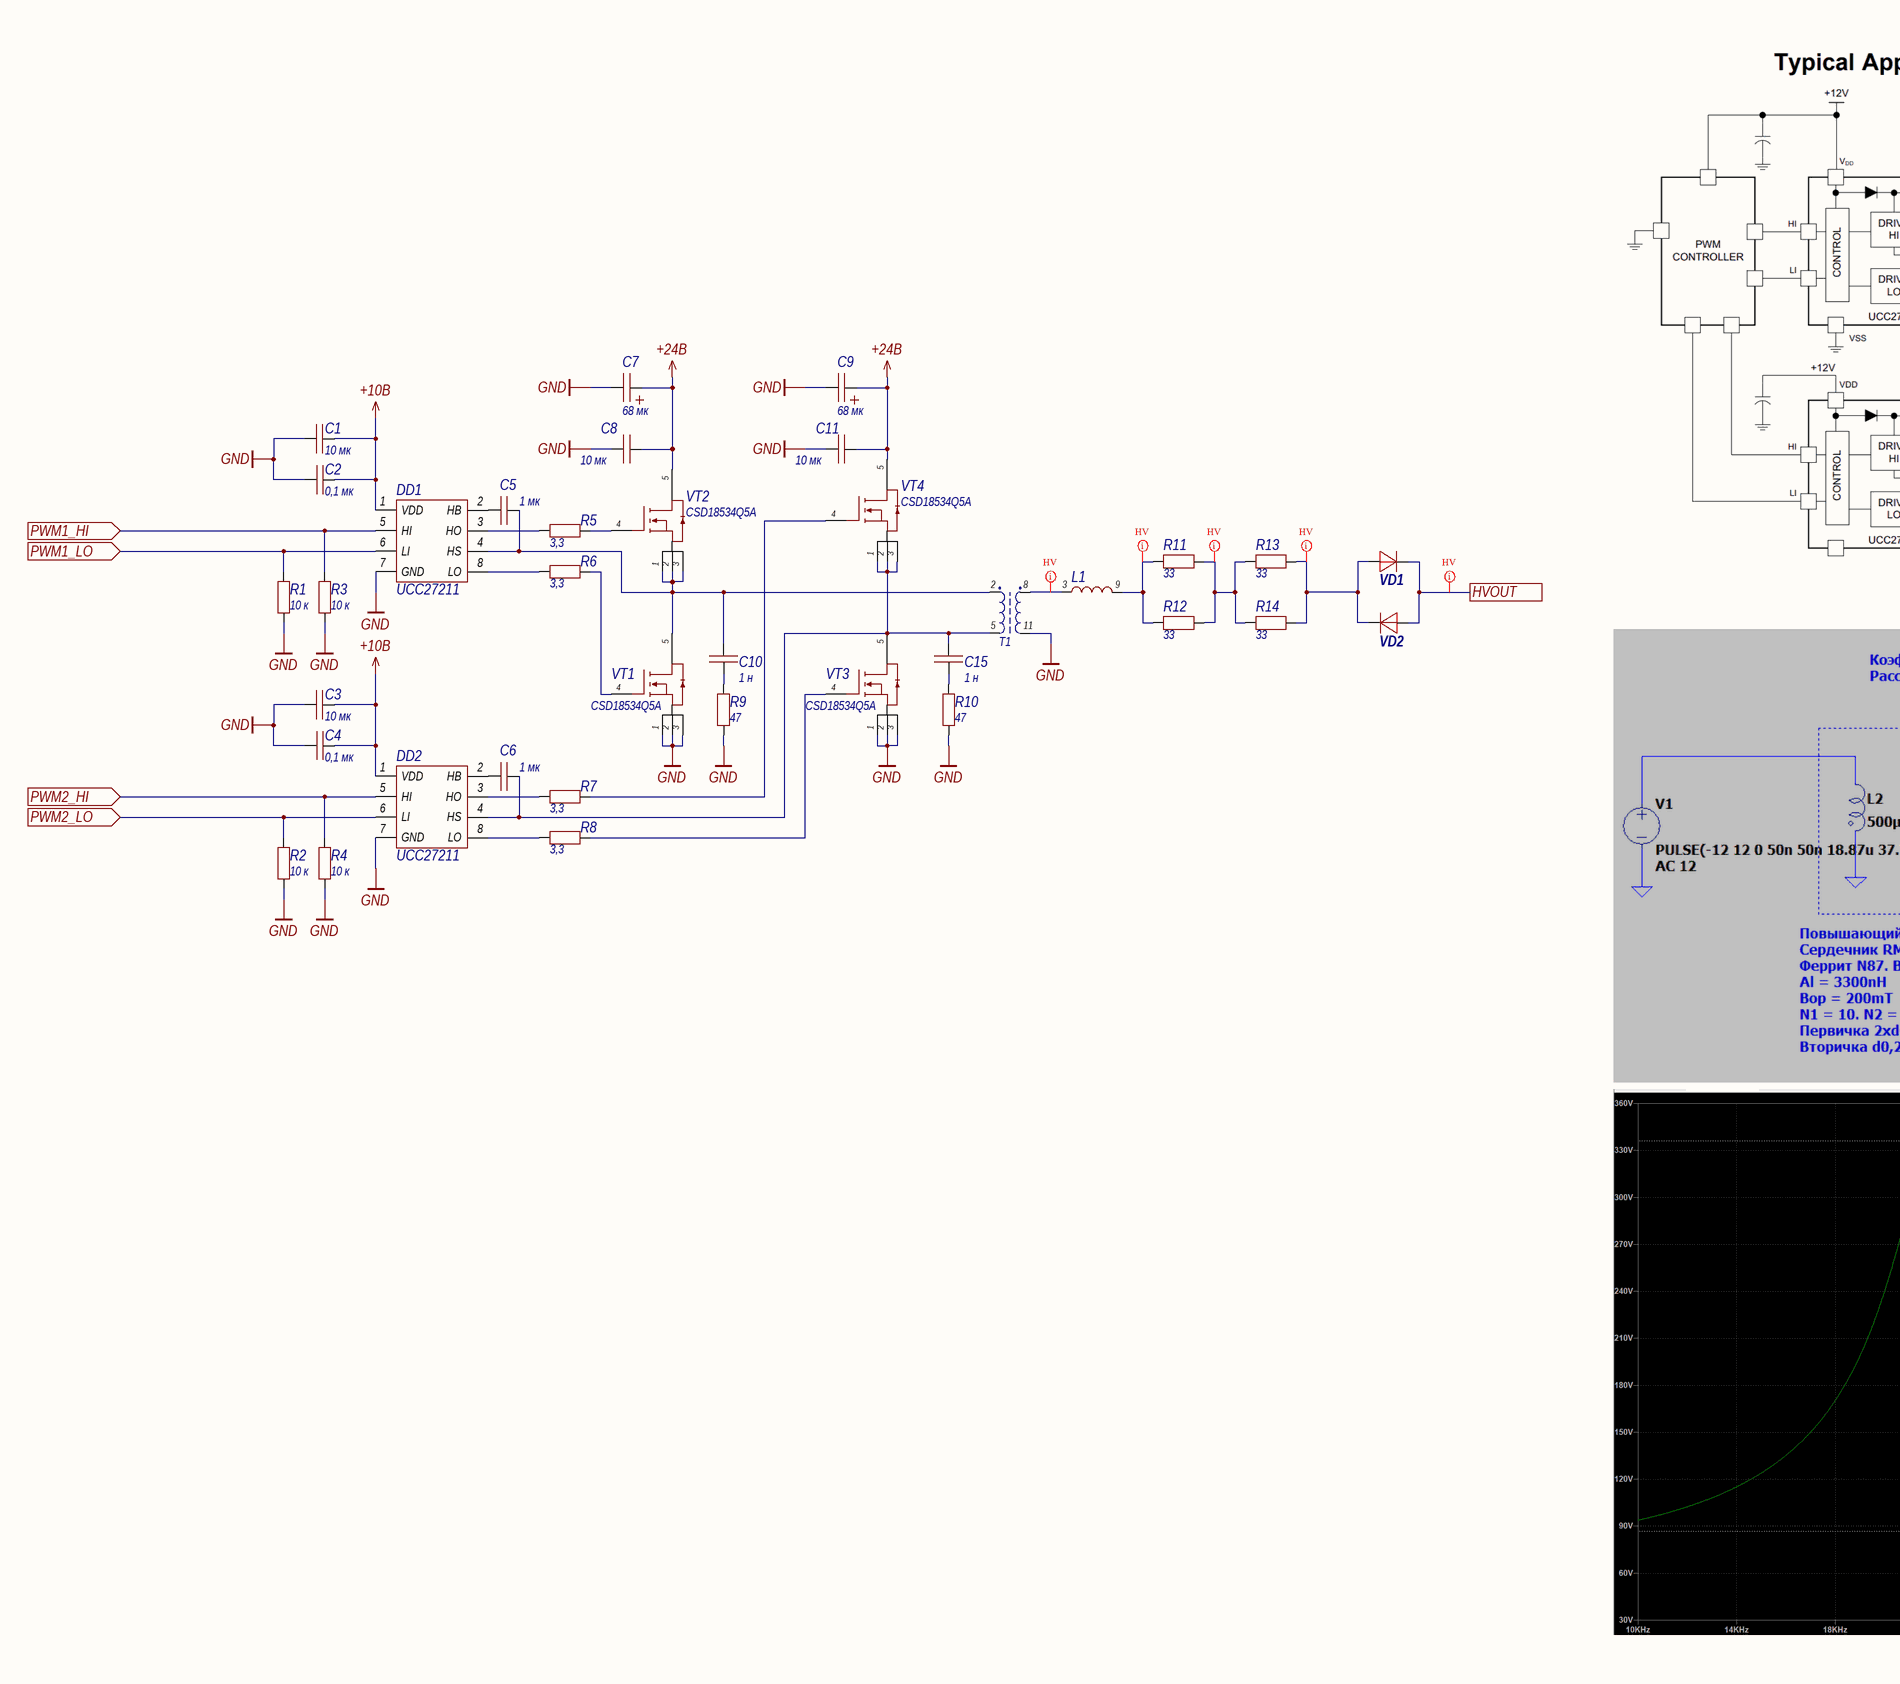
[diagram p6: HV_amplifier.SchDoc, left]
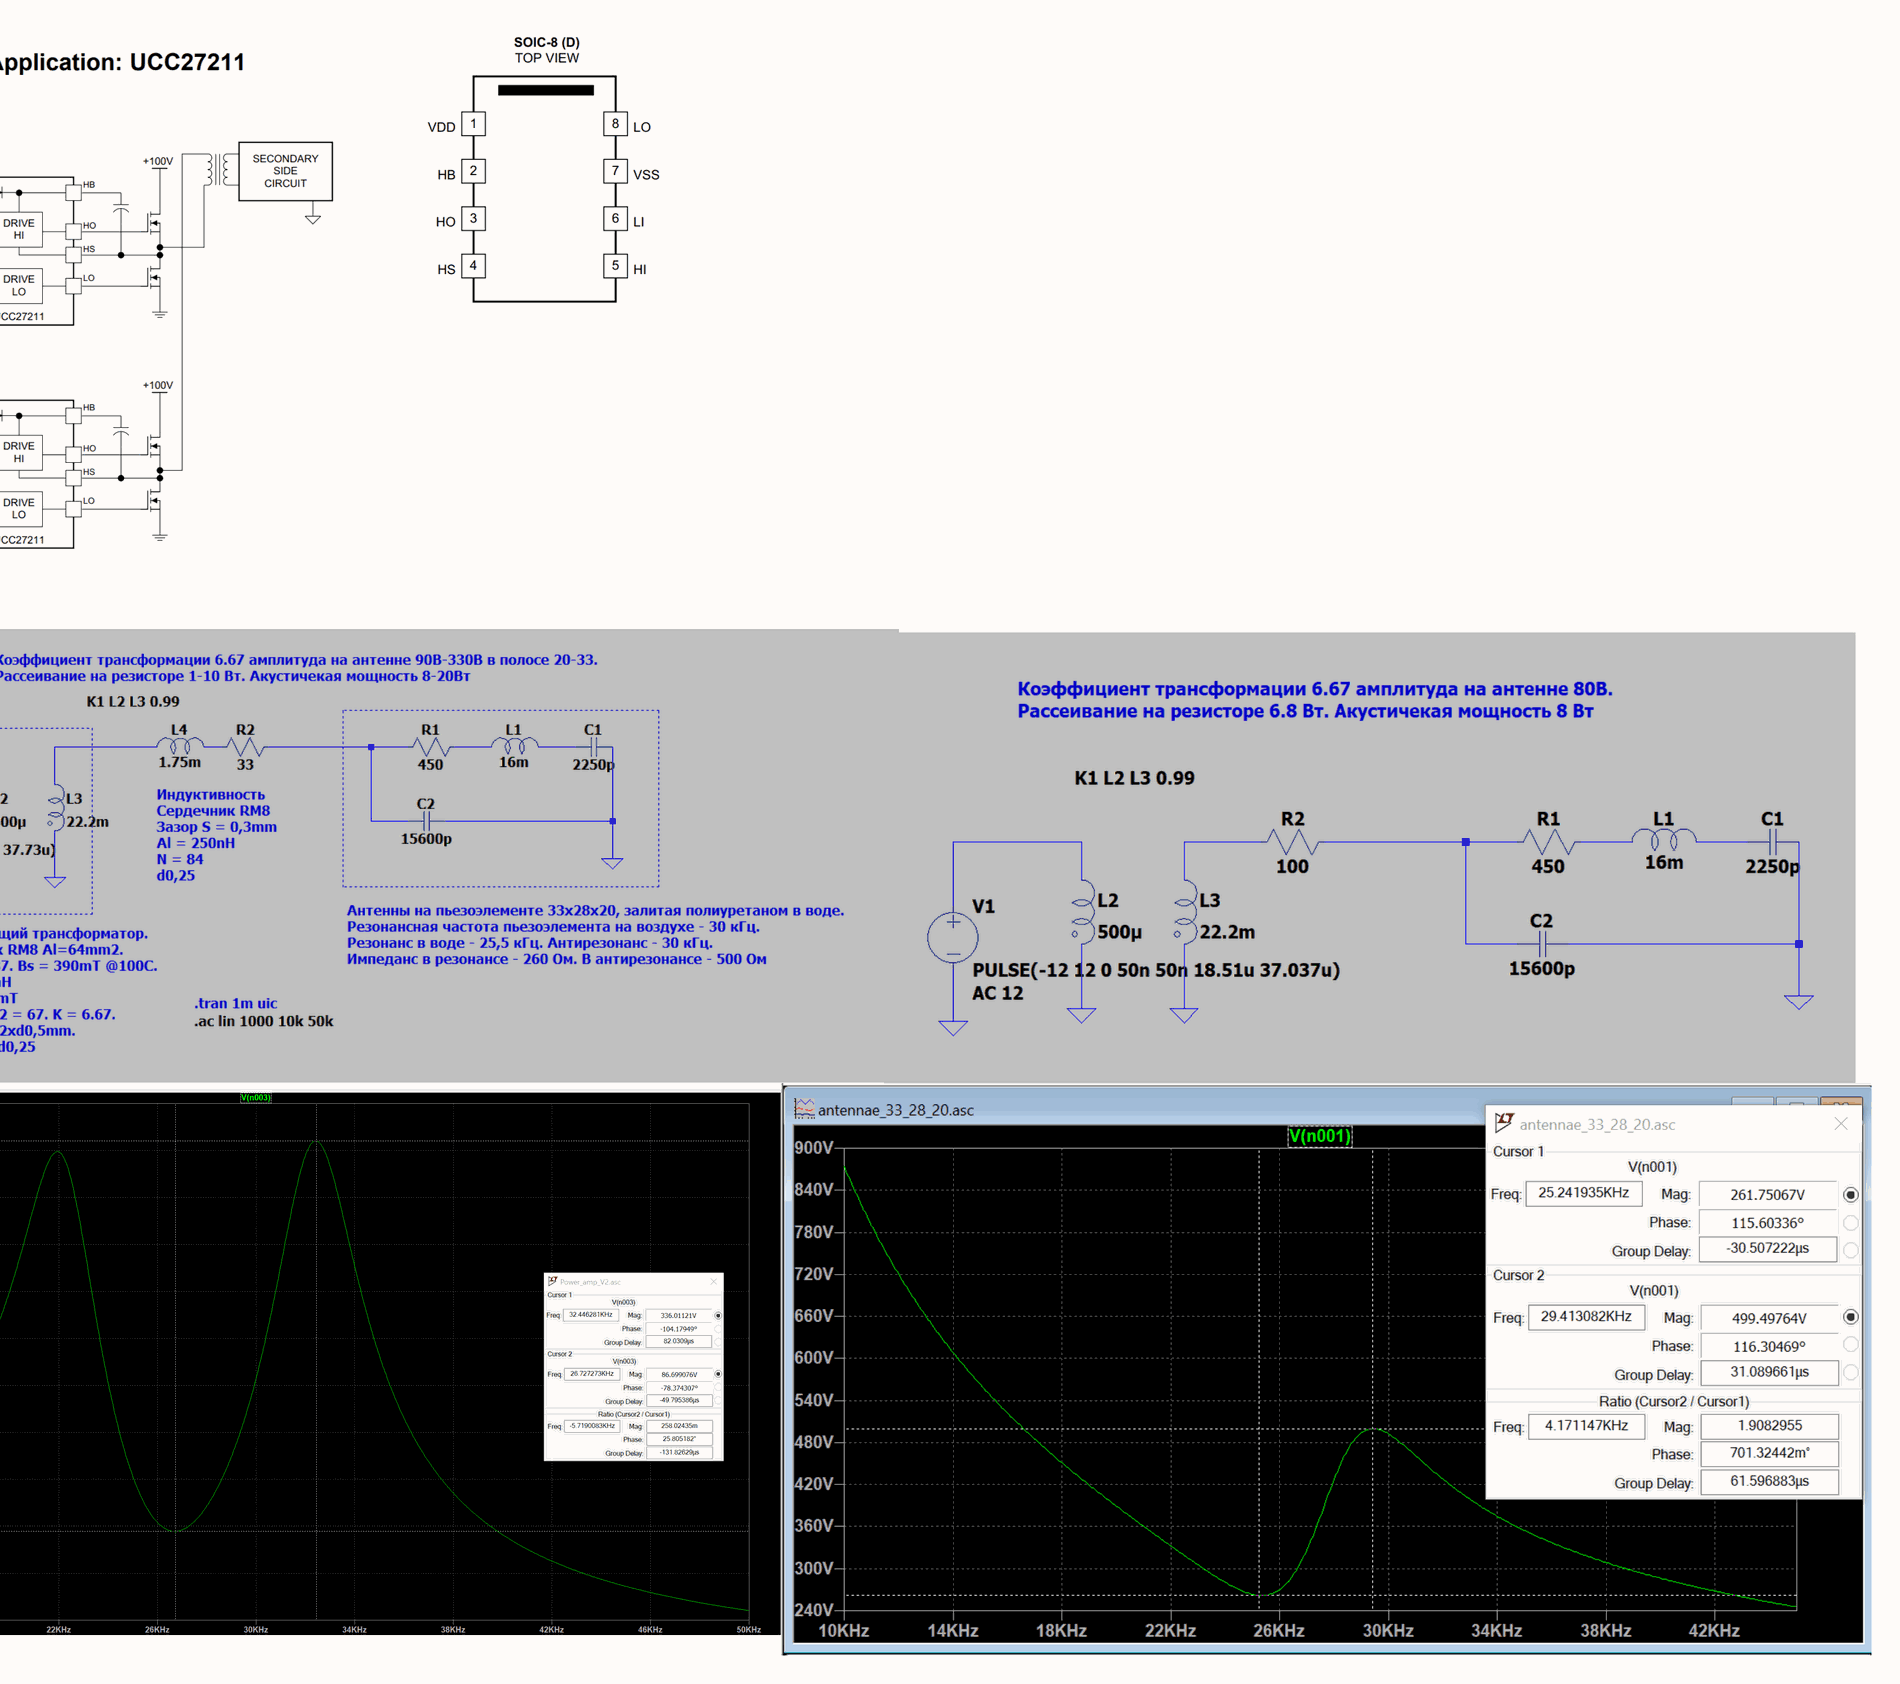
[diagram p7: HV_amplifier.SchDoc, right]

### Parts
C1  value 10 мк  [1210C]  (hidden comment: Capacitor)
C2  value 0,1 мк  [0603C]  (hidden comment: Capacitor)
C3  value 10 мк  [1210C]  (hidden comment: Capacitor)
C4  value 0,1 мк  [0603C]  (hidden comment: Capacitor)
C5  value 1 мк  [0603C]  (hidden comment: Capacitor)
C6  value 1 мк  [0603C]  (hidden comment: Capacitor)
C7  value 68 мк  [CAP_SMD_10x12,7]  (hidden comment: Capacitor)
C8  value 10 мк  [1210C]  (hidden comment: Capacitor)
C9  value 68 мк  [CAP_SMD_10x12,7]  (hidden comment: Capacitor)
C10  value 1 н  [0603C]  (hidden comment: Capacitor)
C11  value 10 мк  [1210C]  (hidden comment: Capacitor)
C15  value 1 н  [0603C]  (hidden comment: Capacitor)
DD1  UCC27211  [SOIC-8]
DD2  UCC27211  [SOIC-8]
L1  Inductance_RM8  [RM8_trans]  (value not drawn)
R1  value 10 к  [0603R]  (hidden comment: Resistor)
R2  value 10 к  [0603R]  (hidden comment: Resistor)
R3  value 10 к  [0603R]  (hidden comment: Resistor)
R4  value 10 к  [0603R]  (hidden comment: Resistor)
R5  value 3,3  [0603R]  (hidden comment: Resistor)
R6  value 3,3  [0603R]  (hidden comment: Resistor)
R7  value 3,3  [0603R]  (hidden comment: Resistor)
R8  value 3,3  [0603R]  (hidden comment: Resistor)
R9  value 47  [0805R]  (hidden comment: Resistor)
R10  value 47  [0805R]  (hidden comment: Resistor)
R11  value 33  [2512R]  (hidden comment: Resistor)
R12  value 33  [2512R]  (hidden comment: Resistor)
R13  value 33  [2512R]  (hidden comment: Resistor)
R14  value 33  [2512R]  (hidden comment: Resistor)
T1  Transformer_RM8  [RM8_trans]  (value not drawn)
VD1  SMA4007  [SMA]  (value not drawn)
VD2  SMA4007  [SMA]  (value not drawn)
VT1  CSD18534Q5A  [SON-8_5x6]
VT2  CSD18534Q5A  [SON-8_5x6]
VT3  CSD18534Q5A  [SON-8_5x6]
VT4  CSD18534Q5A  [SON-8_5x6]

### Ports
HVOUT, PWM1_HI (in), PWM1_LO (in), PWM2_HI (in), PWM2_LO (in)

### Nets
+10В: C1.1 C2.2 C3.1 C4.2 DD1.1(VDD) DD2.1(VDD)
+24В: C7.1 C8.2 C9.1 C11.2 VT2.5 VT4.5
GND: C1.2 C2.1 C3.2 C4.1 C7.2 C8.1 C9.2 C11.1 DD1.7(GND) DD2.7(GND) R1.1 R2.1 R3.1 R4.1 R9.1 R10.1 T1.11 VT1.1 VT1.2 VT1.3 VT3.1 VT3.2 VT3.3
ANT1: VD1.2 VD2.1 ; port HVOUT
PWM1_HI: DD1.5(HI) R3.2 ; port PWM1_HI
PWM1_LO: DD1.6(LI) R1.2 ; port PWM1_LO
PWM2_HI: DD2.5(HI) R4.2 ; port PWM2_HI
PWM2_LO: DD2.6(LI) R2.2 ; port PWM2_LO
NetC5_1: C5.1 DD1.2(HB)
NetC5_2: C5.2 C10.2 DD1.4(HS) T1.2 VT1.5 VT2.1 VT2.2 VT2.3
NetC6_1: C6.1 DD2.2(HB)
NetC6_2: C6.2 C15.2 DD2.4(HS) T1.5 VT3.5 VT4.1 VT4.2 VT4.3
NetC10_1: C10.1 R9.2
NetC15_1: C15.1 R10.2
NetDD1_3: DD1.3(HO) R5.1
NetDD1_8: DD1.8(LO) R6.1
NetDD2_3: DD2.3(HO) R7.1
NetDD2_8: DD2.8(LO) R8.1
NetL1_3: L1.3 T1.8
NetL1_9: L1.9 R11.1 R12.1
NetR5_2: R5.2 VT2.4
NetR6_2: R6.2 VT1.4
NetR7_2: R7.2 VT4.4
NetR8_2: R8.2 VT3.4
NetR11_2: R11.2 R12.2 R13.1 R14.1
NetR13_2: R13.2 R14.2 VD1.1 VD2.2

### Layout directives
net class HV; rule Clearance Constraint [Clearance = 1mm]: ANT1, NetL1_3, NetL1_9, NetR11_2, NetR13_2

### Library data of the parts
C1 C3 C8 C11 = Capacitor_10u_10_35V_X7R_1210C: as C51 on sheet Power
C2 C4 = Capacitor_0,1u_10_50V_X7R_0603C: as C12 on sheet Connectors
C5 C6 = Capacitor_1u_10_25V_X7R_0603C: as C59 on sheet Power
C7 C9 = 50SVPF68M: Конденсатор алюминиевый полимерный 68мкФ 50В ±20% (10х12.6мм) для поверхностного монтажа 0.02Ом 4300мА 5000час 105°С; Tolerance: 20; Voltage (V): 50; Type: SMD Aluminum; Capacity (uF): 68; Автор: glebmih
C10 C15 = Capacitor_1n_5_50V_NP0_0603C: as C20 on sheet Analog_Filter
DD1 DD2 = UCC27211: Полумостовой драйвер затвора для mosfet транзисторов; Автор: glebmih
L1 = Inductance_RM8: Индуктивность на сердечнике RM8; Автор: glebmih
R1-R4 = Resistor_10k_1_0603: Резистор номиналом 10 кОм 1%
R5-R8 = Resistor_3.3_1_0603: Резистор номиналом 3,3 Ом 1%
R9 R10 = Resistor_47_1_0805: Резистор номиналом 47 Ом 1%; Автор: glebmih
R11-R14 = Resistor_33_1_2512: Резистор номиналом 33 Ом 1%; Автор: glebmih
T1 = Transformer_RM8: Трансформатор на сердечнике RM8; Автор: glebmih
VD1 VD2 = SMA4007: Выпрямительный диод на 1000 В, ном. ток 1 А А; Voltage (V): 1000; Current: 1 А; Автор: glebmih
VT1-VT4 = CSD18534Q5A: N-канальный MOSFET, 60 В, 50 А; Voltage (V): 60 В; Current (A): 50 А; Автор: glebmih

## Sheet MCU.SchDoc: ГАНС с короткой или ультракороткой базой
size 420 x 297 mm; SheetNumber: 4; SheetTotal: 6
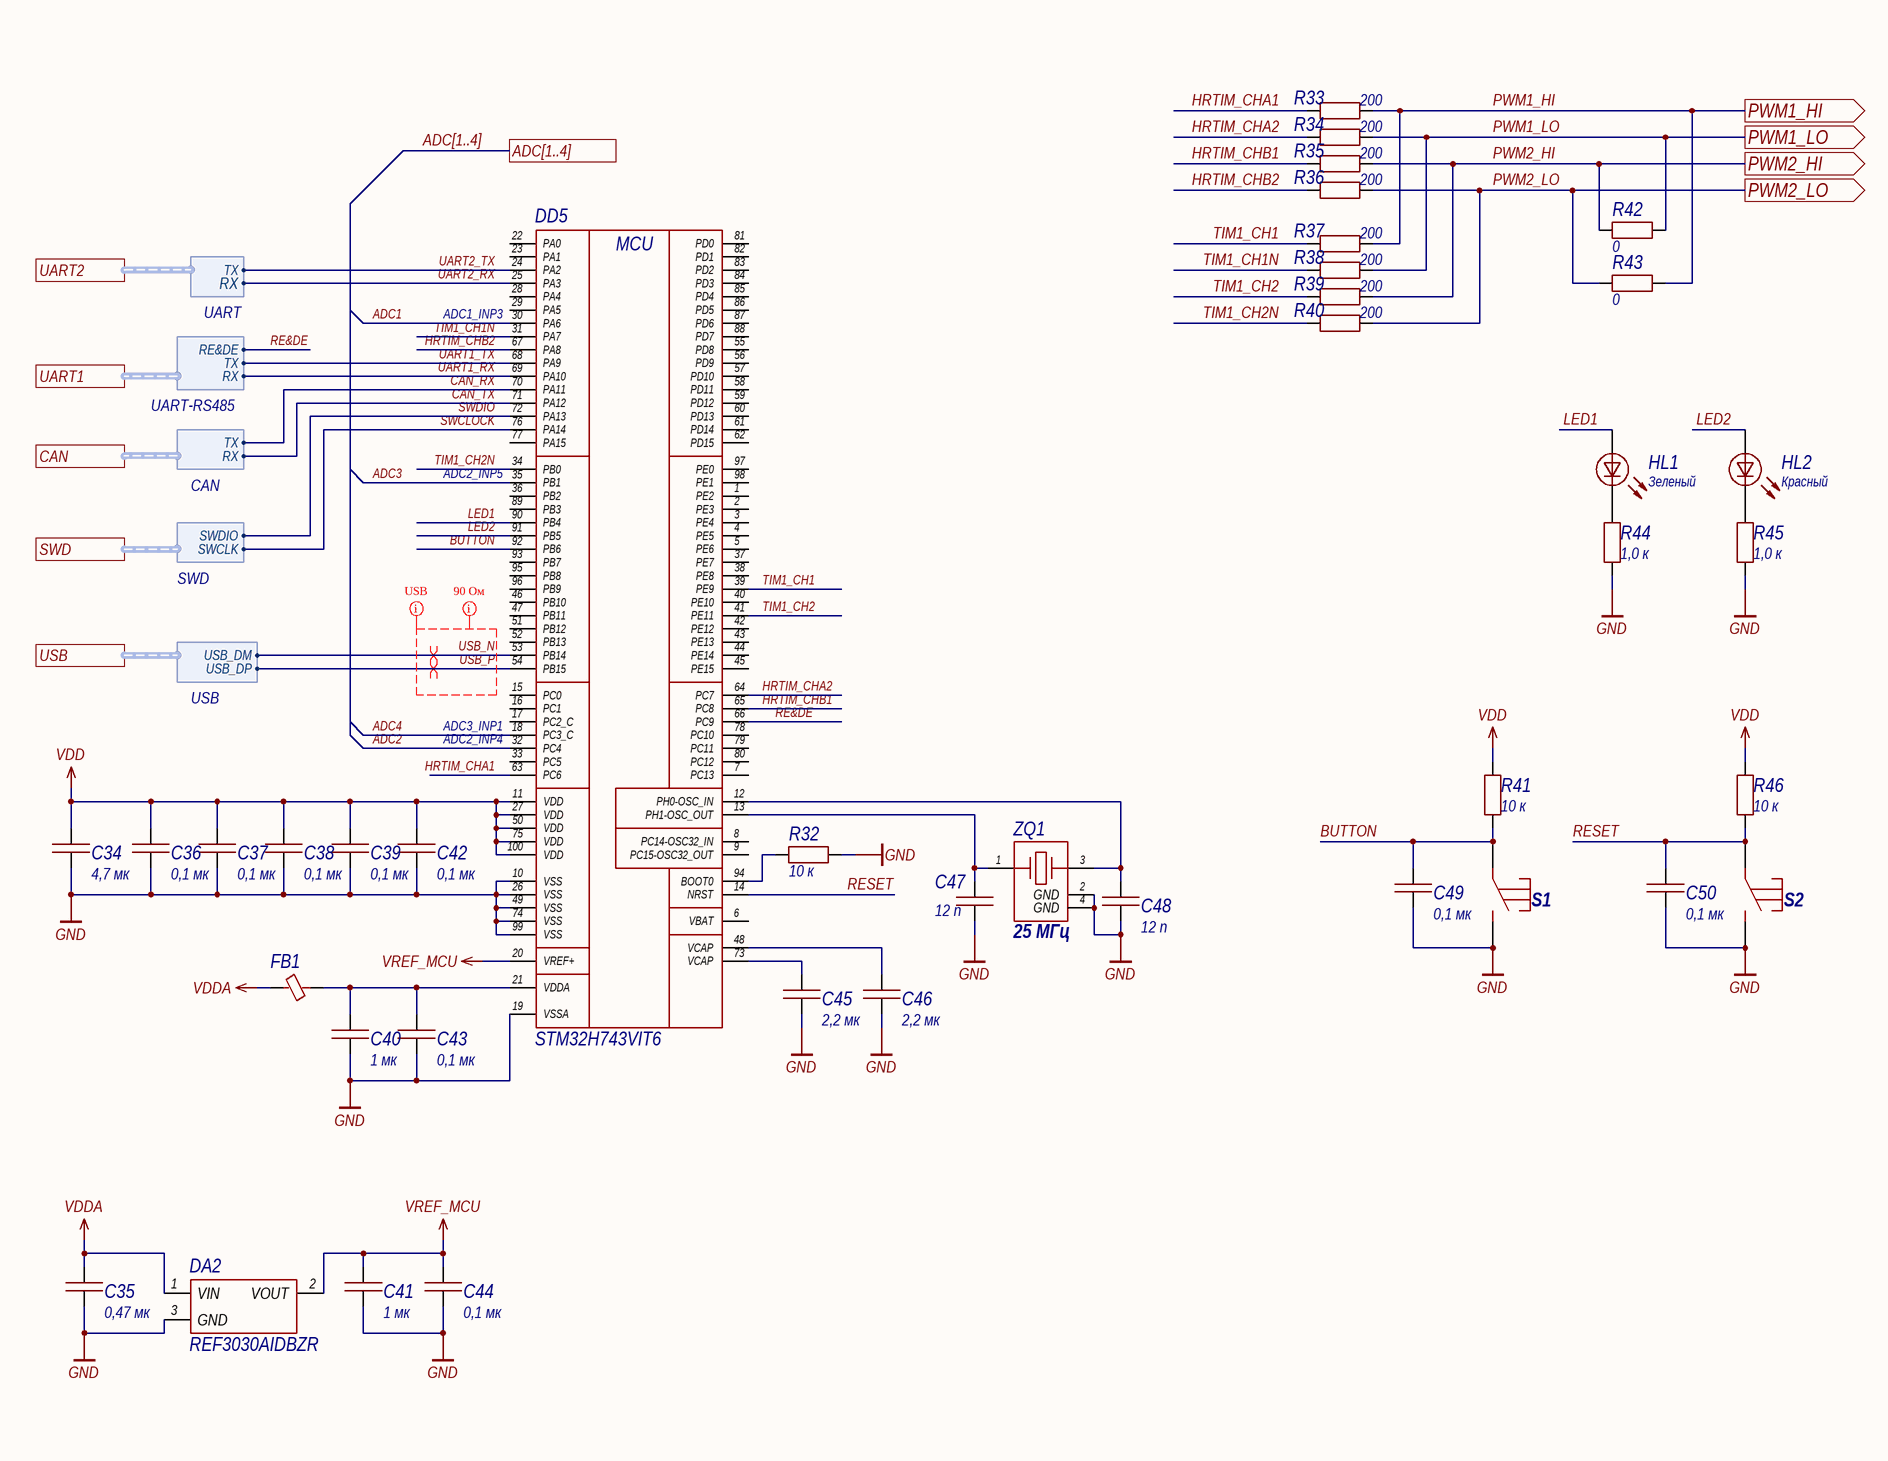
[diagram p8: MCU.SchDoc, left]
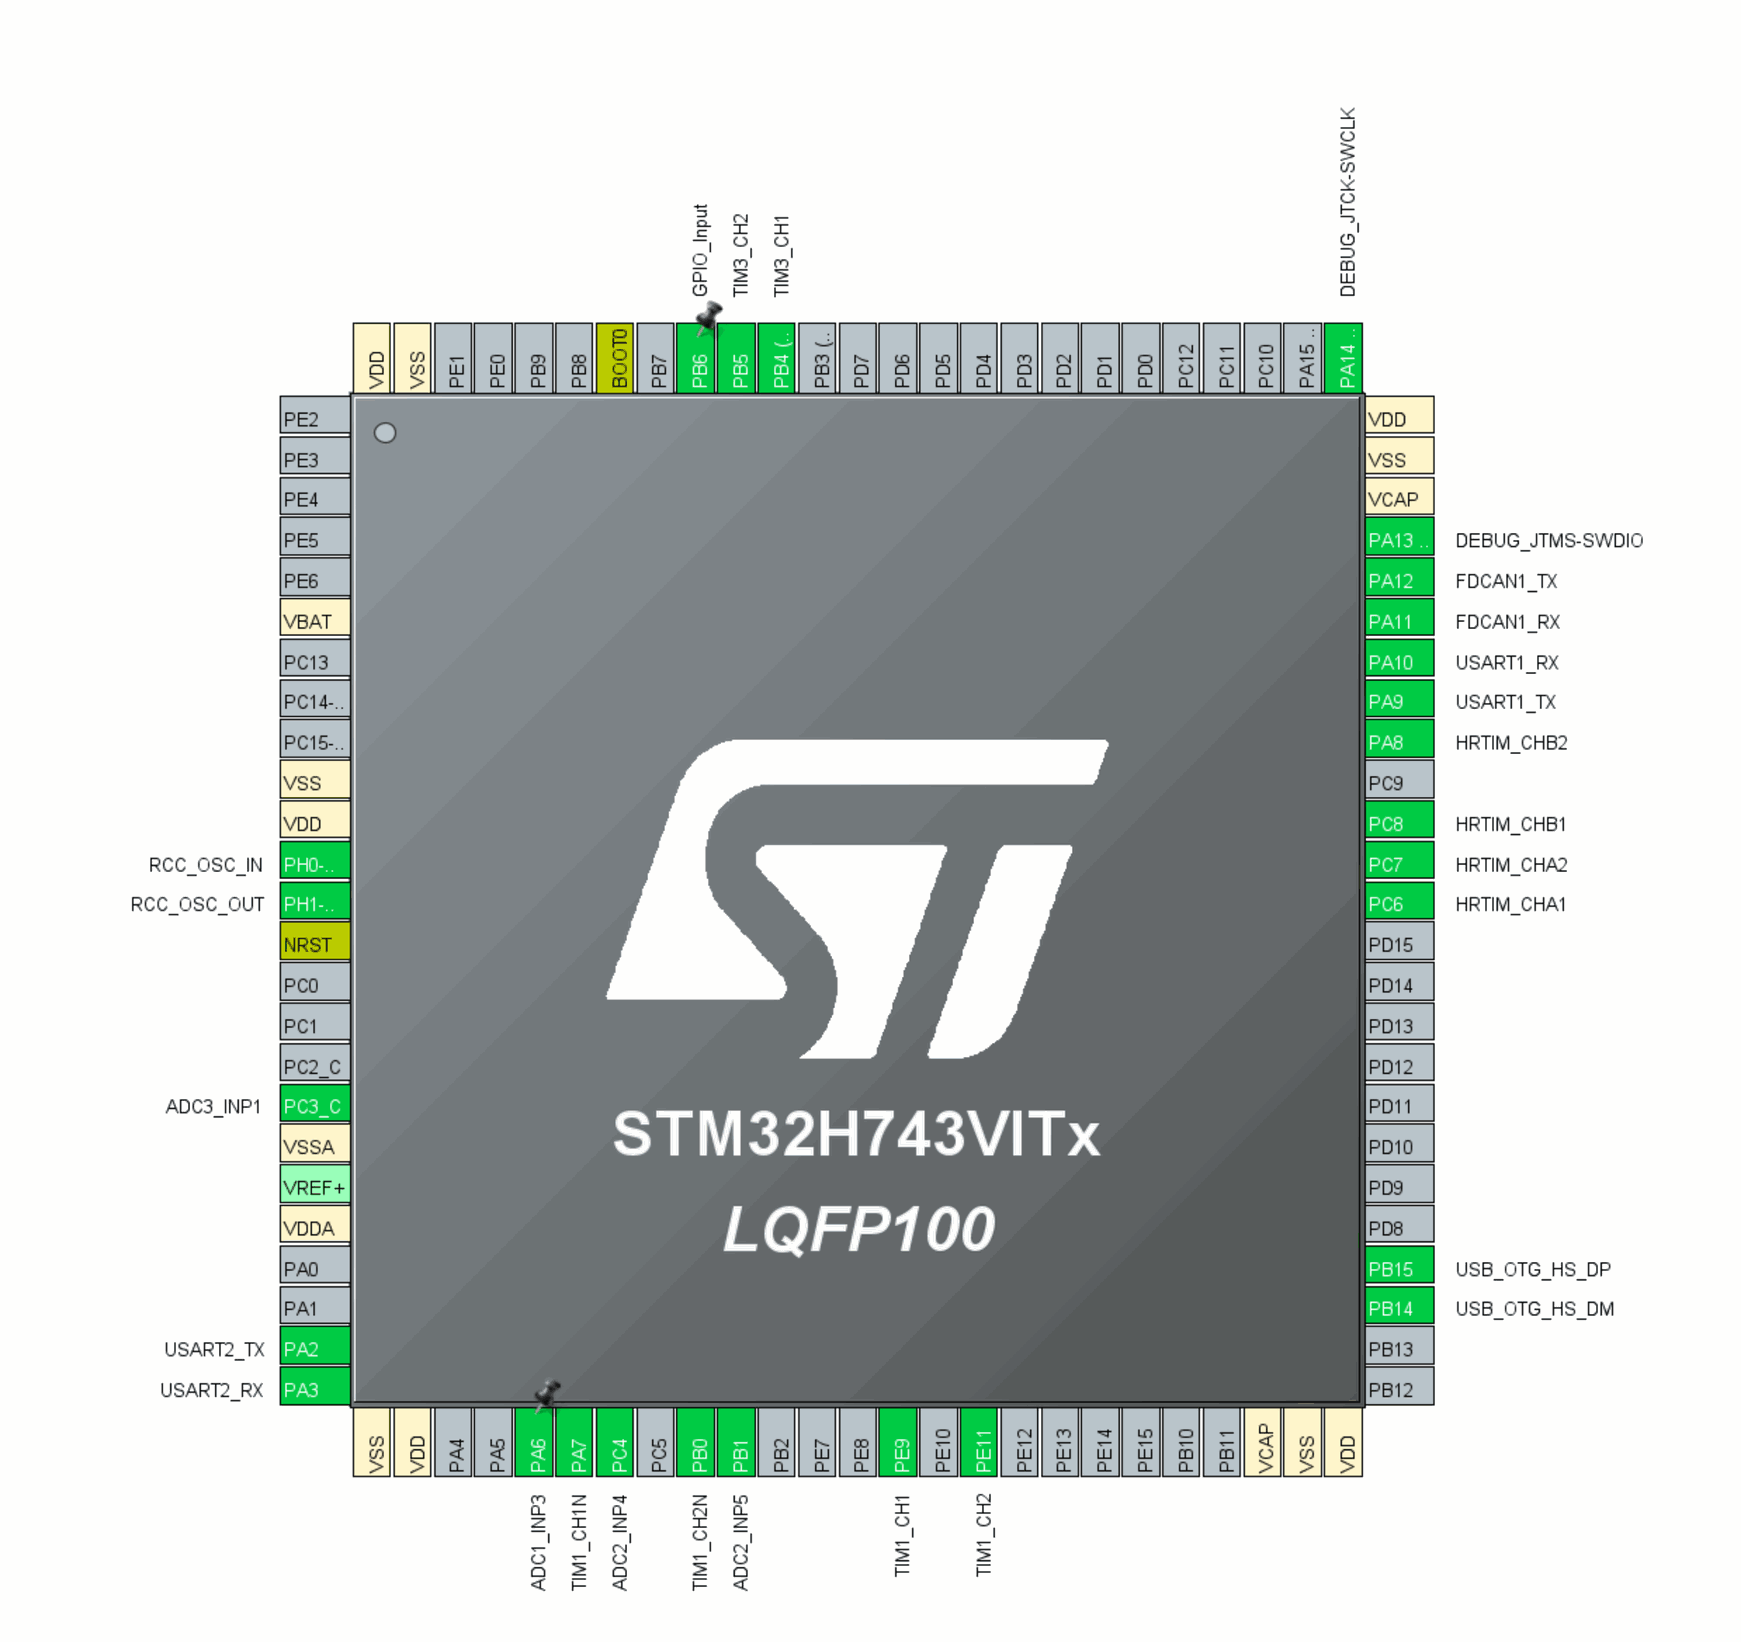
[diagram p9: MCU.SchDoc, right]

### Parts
C34  value 4,7 мк  [1206C]  (hidden comment: Capacitor)
C35  value 0,47 мк  [0603C]  (hidden comment: Capacitor)
C36  value 0,1 мк  [0603C]  (hidden comment: Capacitor)
C37  value 0,1 мк  [0603C]  (hidden comment: Capacitor)
C38  value 0,1 мк  [0603C]  (hidden comment: Capacitor)
C39  value 0,1 мк  [0603C]  (hidden comment: Capacitor)
C40  value 1 мк  [0603C]  (hidden comment: Capacitor)
C41  value 1 мк  [0603C]  (hidden comment: Capacitor)
C42  value 0,1 мк  [0603C]  (hidden comment: Capacitor)
C43  value 0,1 мк  [0603C]  (hidden comment: Capacitor)
C44  value 0,1 мк  [0603C]  (hidden comment: Capacitor)
C45  value 2,2 мк  [1206C]  (hidden comment: Capacitor)
C46  value 2,2 мк  [1206C]  (hidden comment: Capacitor)
C47  value 12 п  [0603C]  (hidden comment: Capacitor)
C48  value 12 п  [0603C]  (hidden comment: Capacitor)
C49  value 0,1 мк  [0603C]  (hidden comment: Capacitor)
C50  value 0,1 мк  [0603C]  (hidden comment: Capacitor)
DA2  REF3030AIDBZR  [SOT23-3]
DD5  STM32H743VIT6  [LQFP100]
FB1  BLM18AG102SN1D  [0603L]  (value not drawn)
HL1  value Зеленый  [0805D]  (hidden comment: LED)
HL2  value Красный  [0805D]  (hidden comment: LED)
R32  value 10 к  [0603R]  (hidden comment: Resistor)
R33  value 200  [0603R]  (hidden comment: Resistor)
R34  value 200  [0603R]  (hidden comment: Resistor)
R35  value 200  [0603R]  (hidden comment: Resistor)
R36  value 200  [0603R]  (hidden comment: Resistor)
R37  value 200  [0603R]  (hidden comment: Resistor)
R38  value 200  [0603R]  (hidden comment: Resistor)
R39  value 200  [0603R]  (hidden comment: Resistor)
R40  value 200  [0603R]  (hidden comment: Resistor)
R41  value 10 к  [0603R]  (hidden comment: Resistor)
R42  value 0  [0603R]  (hidden comment: Resistor)
R43  value 0  [0603R]  (hidden comment: Resistor)
R44  value 1,0 к  [0603R]  (hidden comment: Resistor)
R45  value 1,0 к  [0603R]  (hidden comment: Resistor)
R46  value 10 к  [0603R]  (hidden comment: Resistor)
S1  TSS-TD-19XA-XTR  [TSS-TD-19XA-XTR]  (value not drawn)
S2  TSS-TD-19XA-XTR  [TSS-TD-19XA-XTR]  (value not drawn)
ZQ1  value 25 МГц  [X322525MOB4SI]  (hidden comment: X322525MOB4SI)

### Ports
ADC[1..4], CAN (harness CAN), PWM1_HI (out), PWM1_LO (out), PWM2_HI (out), PWM2_LO (out), SWD (harness SWD), UART1 (harness UART-RS485), UART2 (harness UART), USB (harness USB)

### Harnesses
UART: TX, RX
UART-RS485: TX, RX, RE&DE
USB: USB_DM, USB_DP
SWD: SWDIO, SWCLK
CAN: TX, RX

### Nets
GND: C34.1 C35.1 C36.1 C37.1 C38.1 C39.1 C40.1 C41.1 C42.1 C43.1 C44.1 C45.1 C46.1 C47.1 C48.1 C49.1 C50.1 DA2.3(GND) DD5.10(VSS) DD5.19(VSSA) DD5.26(VSS) DD5.49(VSS) DD5.74(VSS) DD5.99(VSS) R32.1 R44.1 R45.1 S1.2 S2.2 ZQ1.2(GND) ZQ1.4(GND)
VDD: C34.2 C36.2 C37.2 C38.2 C39.2 C42.2 DD5.11(VDD) DD5.27(VDD) DD5.50(VDD) DD5.75(VDD) DD5.100(VDD) R41.2 R46.2
VDDA: C35.2 DA2.1(VIN) FB1.1
VREF_MCU: C41.2 C44.2 DA2.2(VOUT) DD5.20(VREF+)
ADC1: DD5.30(PA6)
ADC2: DD5.32(PC4)
ADC3: DD5.35(PB1)
ADC4: DD5.18(PC3_C)
BUTTON: C49.2 DD5.92(PB6) R41.1 S1.1  [project net BUTTON_4]
CAN_RX: DD5.70(PA11) ; port CAN.TX
CAN_TX: DD5.71(PA12) ; port CAN.RX
HRTIM_CHA1: DD5.63(PC6) R33.1  [project net HRTIM_CHA1_4]
HRTIM_CHA2: DD5.64(PC7) R34.1  [project net HRTIM_CHA2_4]
HRTIM_CHB1: DD5.65(PC8) R35.1  [project net HRTIM_CHB1_4]
HRTIM_CHB2: DD5.67(PA8) R36.1  [project net HRTIM_CHB2_4]
LED1: DD5.90(PB4) HL1.1  [project net LED1_4]
LED2: DD5.91(PB5) HL2.1  [project net LED2_4]
PWM1_HI: R33.2 R37.2 R43.2 ; port PWM1_HI
PWM1_LO: R34.2 R38.2 R42.2 ; port PWM1_LO
PWM2_HI: R35.2 R39.2 R42.1 ; port PWM2_HI
PWM2_LO: R36.2 R40.2 R43.1 ; port PWM2_LO
RE&DE: DD5.66(PC9) ; port UART1.RE&DE
RESET: C50.2 DD5.14(NRST) R46.1 S2.1  [project net RESET_4]
SWCLOCK: DD5.76(PA14) ; port SWD.SWCLK
SWDIO: DD5.72(PA13) ; port SWD.SWDIO
TIM1_CH1: DD5.39(PE9) R37.1  [project net TIM1_CH1_4]
TIM1_CH1N: DD5.31(PA7) R38.1  [project net TIM1_CH1N_4]
TIM1_CH2: DD5.41(PE11) R39.1  [project net TIM1_CH2_4]
TIM1_CH2N: DD5.34(PB0) R40.1  [project net TIM1_CH2N_4]
UART1_RX: DD5.69(PA10) ; port UART1.RX
UART1_TX: DD5.68(PA9) ; port UART1.TX
UART2_RX: DD5.25(PA3) ; port UART2.RX
UART2_TX: DD5.24(PA2) ; port UART2.TX
USB_N: DD5.53(PB14) ; port USB.USB_DM
USB_P: DD5.54(PB15) ; port USB.USB_DP
NetC40_2: C40.2 C43.2 DD5.21(VDDA) FB1.2
NetC45_2: C45.2 DD5.73(VCAP)
NetC46_2: C46.2 DD5.48(VCAP)
NetC47_2: C47.2 DD5.13(PH1-OSC_OUT) ZQ1.1
NetC48_2: C48.2 DD5.12(PH0-OSC_IN) ZQ1.3
NetDD5_94: DD5.94(BOOT0) R32.2
NetHL1_2: HL1.2 R44.2
NetHL2_2: HL2.2 R45.2

Not connected (* = marked no-connect by the designer): DD5 1(PE2) 2(PE3) 3(PE4) 4(PE5) 5(PE6) 6(VBAT) 7(PC13) 8(PC14-OSC32_IN) 9(PC15-OSC32_OUT) 15(PC0) 16(PC1) 17(PC2_C) 22(PA0) 23(PA1) 28(PA4) 29(PA5) 33(PC5) 36(PB2) 37(PE7) 38(PE8) 40(PE10) 42(PE12) 43(PE13) 44(PE14) 45(PE15) 46(PB10) 47(PB11) 51(PB12) 52(PB13) 55(PD8) 56(PD9) 57(PD10) 58(PD11) 59(PD12) 60(PD13) 61(PD14) 62(PD15) 77(PA15) 78(PC10) 79(PC11) 80(PC12) 81(PD0) 82(PD1) 83(PD2) 84(PD3) 85(PD4) 86(PD5) 87(PD6) 88(PD7) 89(PB3) 93(PB7) 95(PB8) 96(PB9) 97(PE0) 98(PE1)

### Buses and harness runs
bus ADC[1..4] = port ADC[1..4]

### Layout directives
differential pair; differential pair class 90OhmDiff: USB_N, USB_P
mark named USB: USB_N, USB_P
mark named 90 Ом: USB_N, USB_P

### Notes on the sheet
- (near DD5) ADC1_INP3
- (near DD5) ADC2_INP5
- (near DD5) ADC3_INP1
- (near DD5) ADC2_INP4

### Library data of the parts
C34 = Capacitor_4,7u_10_50V_X7R_1206C: Конденсатор 1206C ёмкостью 4,7 мк 10%, 50 В, X7R; Voltage (V): 50; Capacity (nF): 4700
C35 = Capacitor_0,47u_10_50V_X7R_0603C: Конденсатор 0603C ёмкостью 0,47 мк 10%, 50 В, X7R; Voltage (V): 50; Capacity (nF): 470
C36-C39 C42-C44 C49 C50 = Capacitor_0,1u_10_50V_X7R_0603C: as C12 on sheet Connectors
C40 C41 = Capacitor_1u_10_25V_X7R_0603C: as C59 on sheet Power
C45 C46 = Capacitor_2,2u_10_50V_X7R_1206C: Конденсатор 1206C ёмкостью 2,2 мк 10%, 50 В, X7R; Voltage (V): 50; Capacity (nF): 2200
C47 C48 = Capacitor_12p_5_50V_NP0_0603C: Конденсатор 0603C ёмкостью 12 п 5%, 50 В, NP0; Voltage (V): 50; Capacity (nF): 0,012; Автор: glebmih
DA2 = REF3030AIDBZR: Источник опорного напряжения, 3В; Автор: glebmih
DD5 = STM32H743VIT6: Микроконтроллер, 32-Бит, Cortex-M7, 480МГц, 2Мб Flash, 1Мб SRAM, 82 I/O; MF: STMicroelectronics; Автор: glebmih
FB1 = BLM18AG102SN1D: Дроссель подавления ЭМП; Автор: glebmih
HL1 HL2 = LED: Светодиод
R32 R41 R46 = Resistor_10k_1_0603: Резистор номиналом 10 кОм 1%
R33-R40 = Resistor_200_1_0603: Резистор номиналом 200 Ом 1%
R42 R43 = Resistor_0_5_0603: Резистор номиналом 0 Ом 5%; Автор: glebmih
R44 R45 = Resistor_1.0k_1_0603: Резистор номиналом 1,0 кОм 1%
S1 S2 = TSS-TD-19XA-XTR: Тактовая кнопка; Автор: glebmih
ZQ1 = X322525MOB4SI: Кварцевый резонатор SMD 25 МГц ±10ppm SMD-3225_4P; Автор: rreali

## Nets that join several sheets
+5В: Connectors (C12.2 C67.1 DD6.8 DD7.3), Power (11 pins)
+10В: Power (7 pins), HV_amplifier (6 pins)
+24В: Connectors (VD6.2 VT6.1 VT6.2 VT6.3), Power (6 pins), HV_amplifier (6 pins)
GND: Connectors (16 pins), 1 (13 pins), 2 (13 pins), 3 (13 pins), 4 (13 pins), Power (20 pins), HV_amplifier (23 pins), MCU (31 pins)
VDD: Connectors (VD5.5 VD7.5 VT5.2), Power (C56.2 D1.2 HL3.1), MCU (13 pins)
VDDA: 1 (7 pins), 2 (7 pins), 3 (7 pins), 4 (7 pins), Power (C63.2 DA5.5), MCU (C35.2 DA2.1 FB1.1)
ADC1: 1 (R31A.2), MCU (DD5.30)
ADC2: 2 (R31B.2), MCU (DD5.32)
ADC3: 3 (R31C.2), MCU (DD5.35)
ADC4: 4 (R31D.2), MCU (DD5.18)
ANT1: Connectors (XP5.1), 1 (C19A.1), HV_amplifier (VD1.2 VD2.1)
ANT2: Connectors (XP6.1), 2 (C19B.1)
ANT3: Connectors (XP7.1), 3 (C19C.1)
ANT4: Connectors (XP8.1), 4 (C19D.1)
CAN_RX: Connectors (DD7.1), MCU (DD5.70)
CAN_TX: Connectors (DD7.4), MCU (DD5.71)
PWM1_HI: HV_amplifier (DD1.5 R3.2), MCU (R33.2 R37.2 R43.2)
PWM1_LO: HV_amplifier (DD1.6 R1.2), MCU (R34.2 R38.2 R42.2)
PWM2_HI: HV_amplifier (DD2.5 R4.2), MCU (R35.2 R39.2 R42.1)
PWM2_LO: HV_amplifier (DD2.6 R2.2), MCU (R36.2 R40.2 R43.1)
RE&DE: Connectors (DD6.2 DD6.3), MCU (DD5.66)
SWCLOCK: Connectors (VD5.1 XP3.3), MCU (DD5.76)
SWDIO: Connectors (VD5.6 XP3.2), MCU (DD5.72)
UART1_RX: Connectors (DD6.1), MCU (DD5.69)
UART1_TX: Connectors (DD6.4), MCU (DD5.68)
UART2_RX: Connectors (VD5.3 XP3.6), MCU (DD5.25)
UART2_TX: Connectors (VD5.4 XP3.5), MCU (DD5.24)
USB_N: Connectors (VD7.6 XP4.1), MCU (DD5.53)
USB_P: Connectors (VD7.1 XP4.2), MCU (DD5.54)

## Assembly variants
01: not fitted C12 DD7 R37 R38 R39 R40 R42 R43 R57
